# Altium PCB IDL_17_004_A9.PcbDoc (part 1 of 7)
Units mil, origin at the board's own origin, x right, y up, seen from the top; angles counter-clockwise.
Board outline 9493.25 x 7199.68 mil, 6 copper layers (Top Layer - SIG1, Layer 2 - GND1, Layer 3 - PWR1, Layer 4 - PWR2, Layer 5 - GND2, Bottom Layer - SIG2), stack 60.592 mil thick; 403 components, 274 nets, 1834 pads, 1849 vias.
Unrouted connection lines stored in the file: 1.
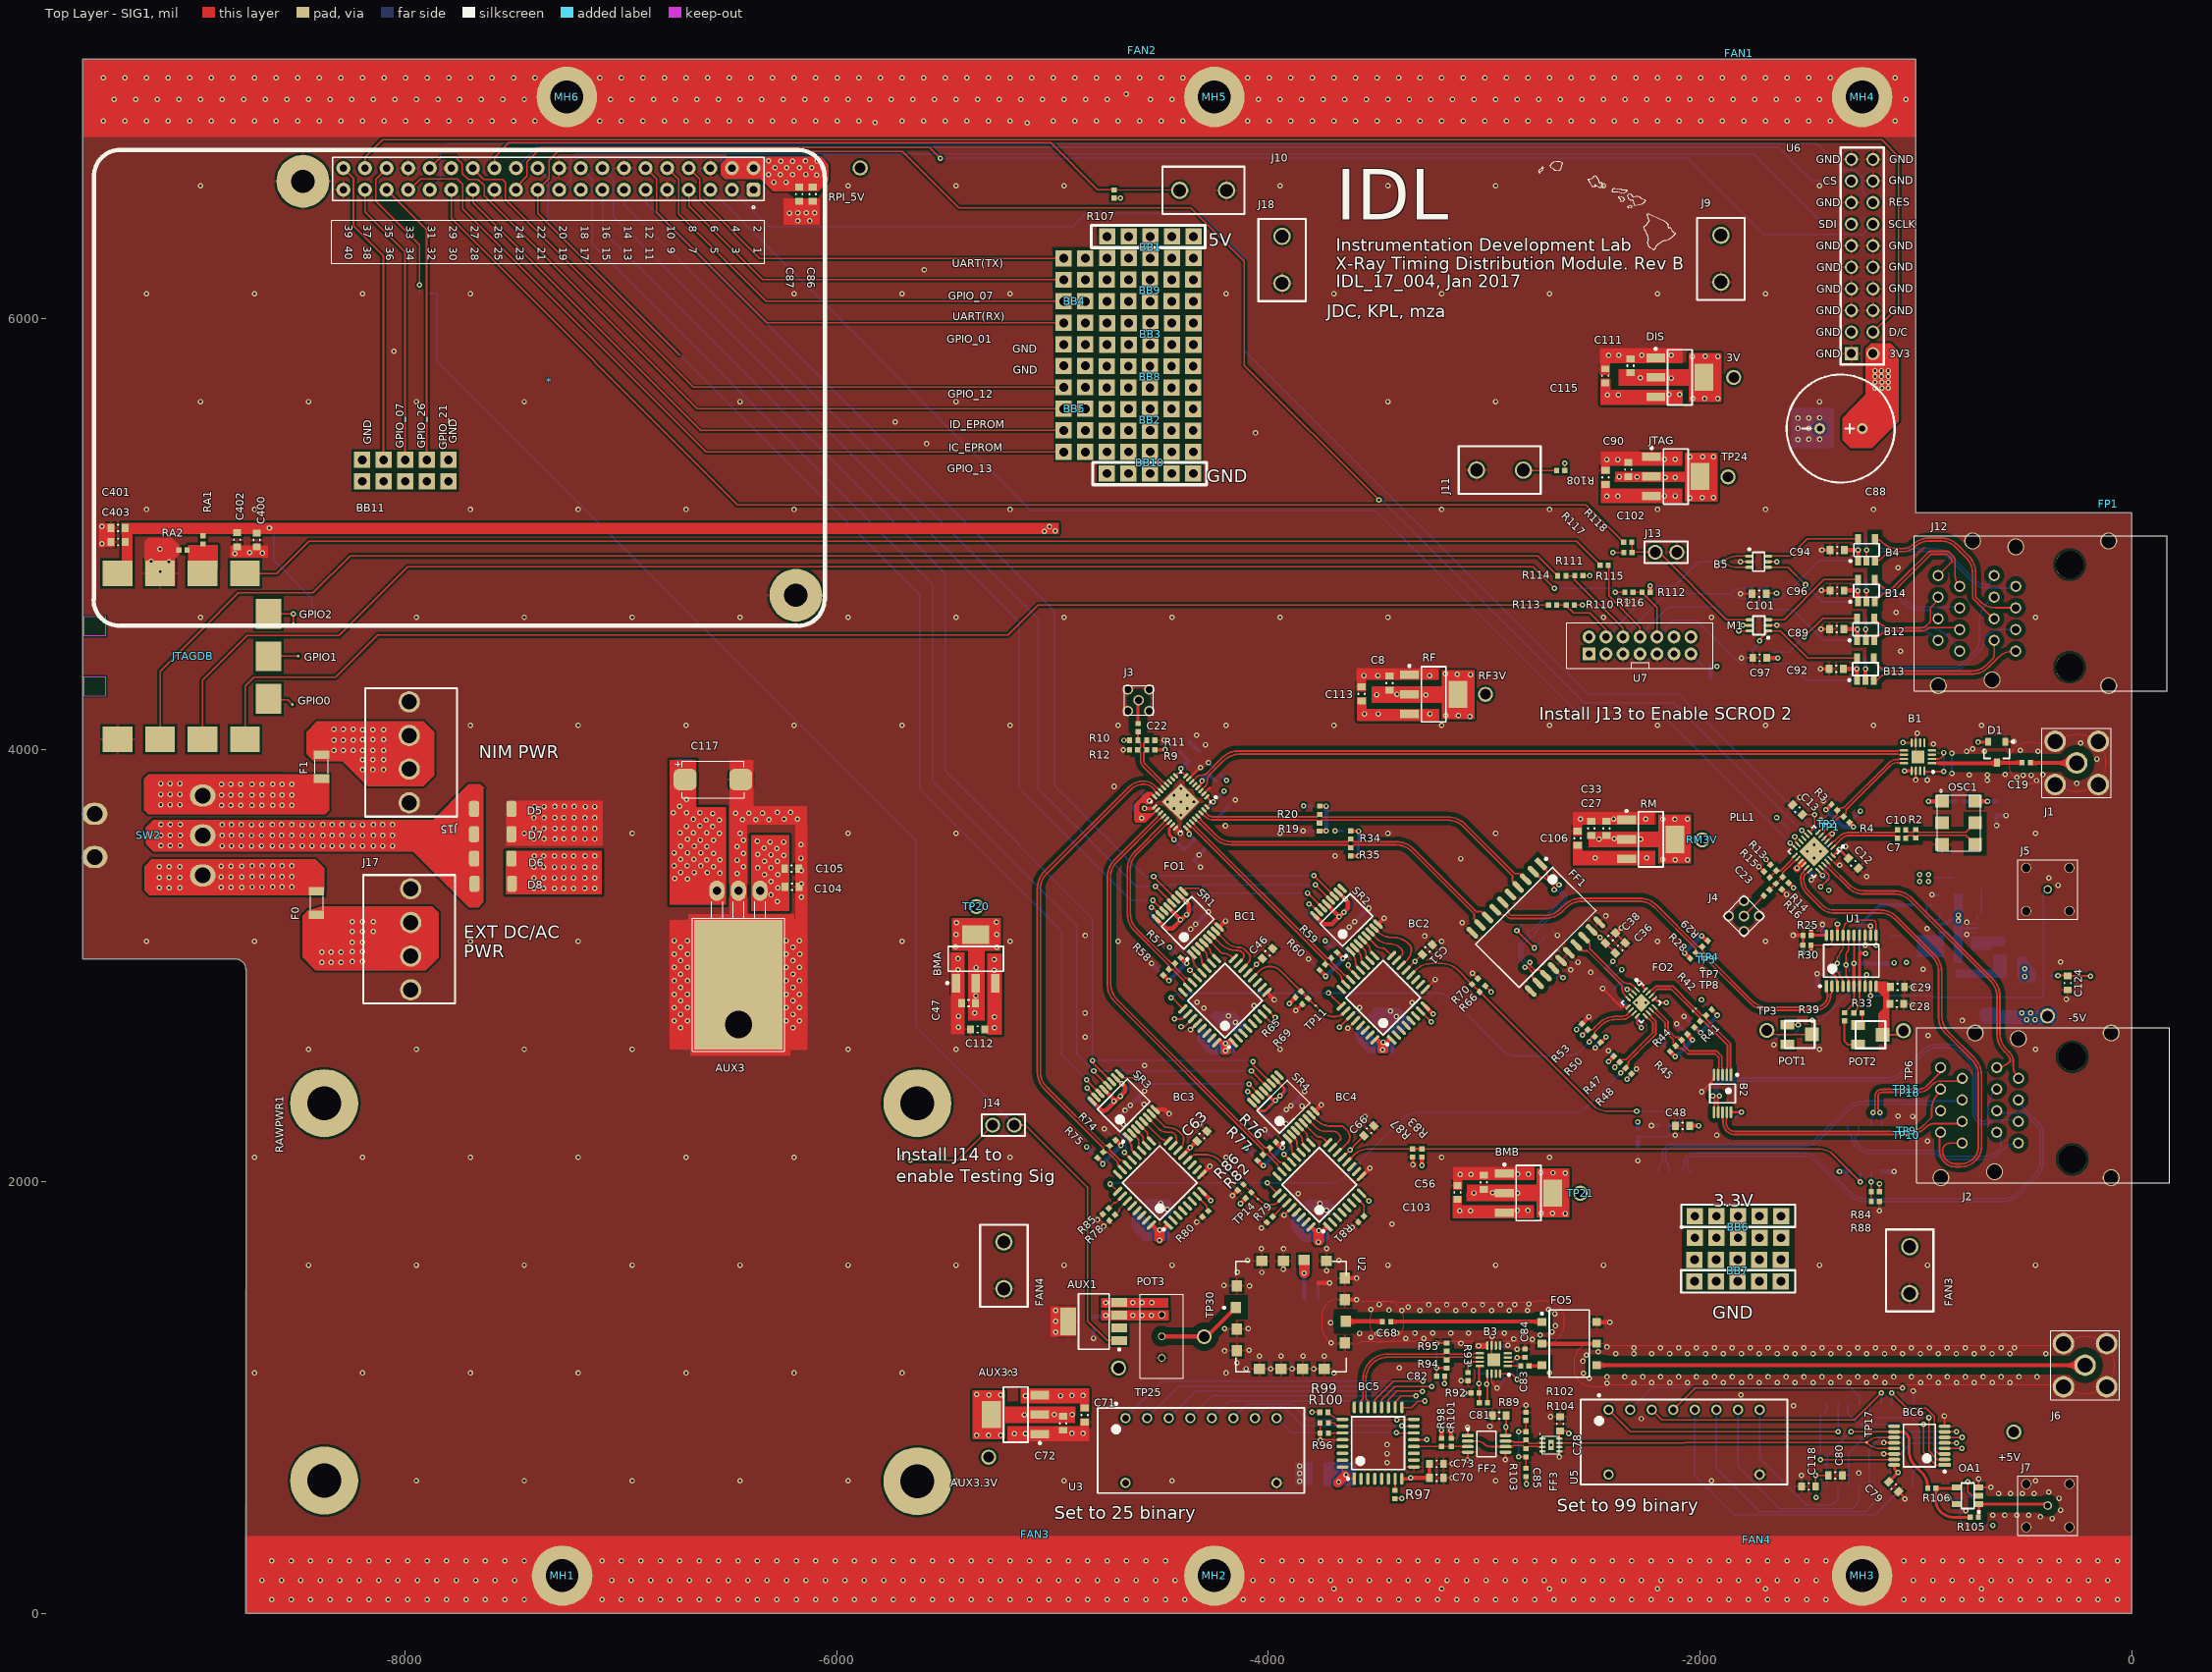
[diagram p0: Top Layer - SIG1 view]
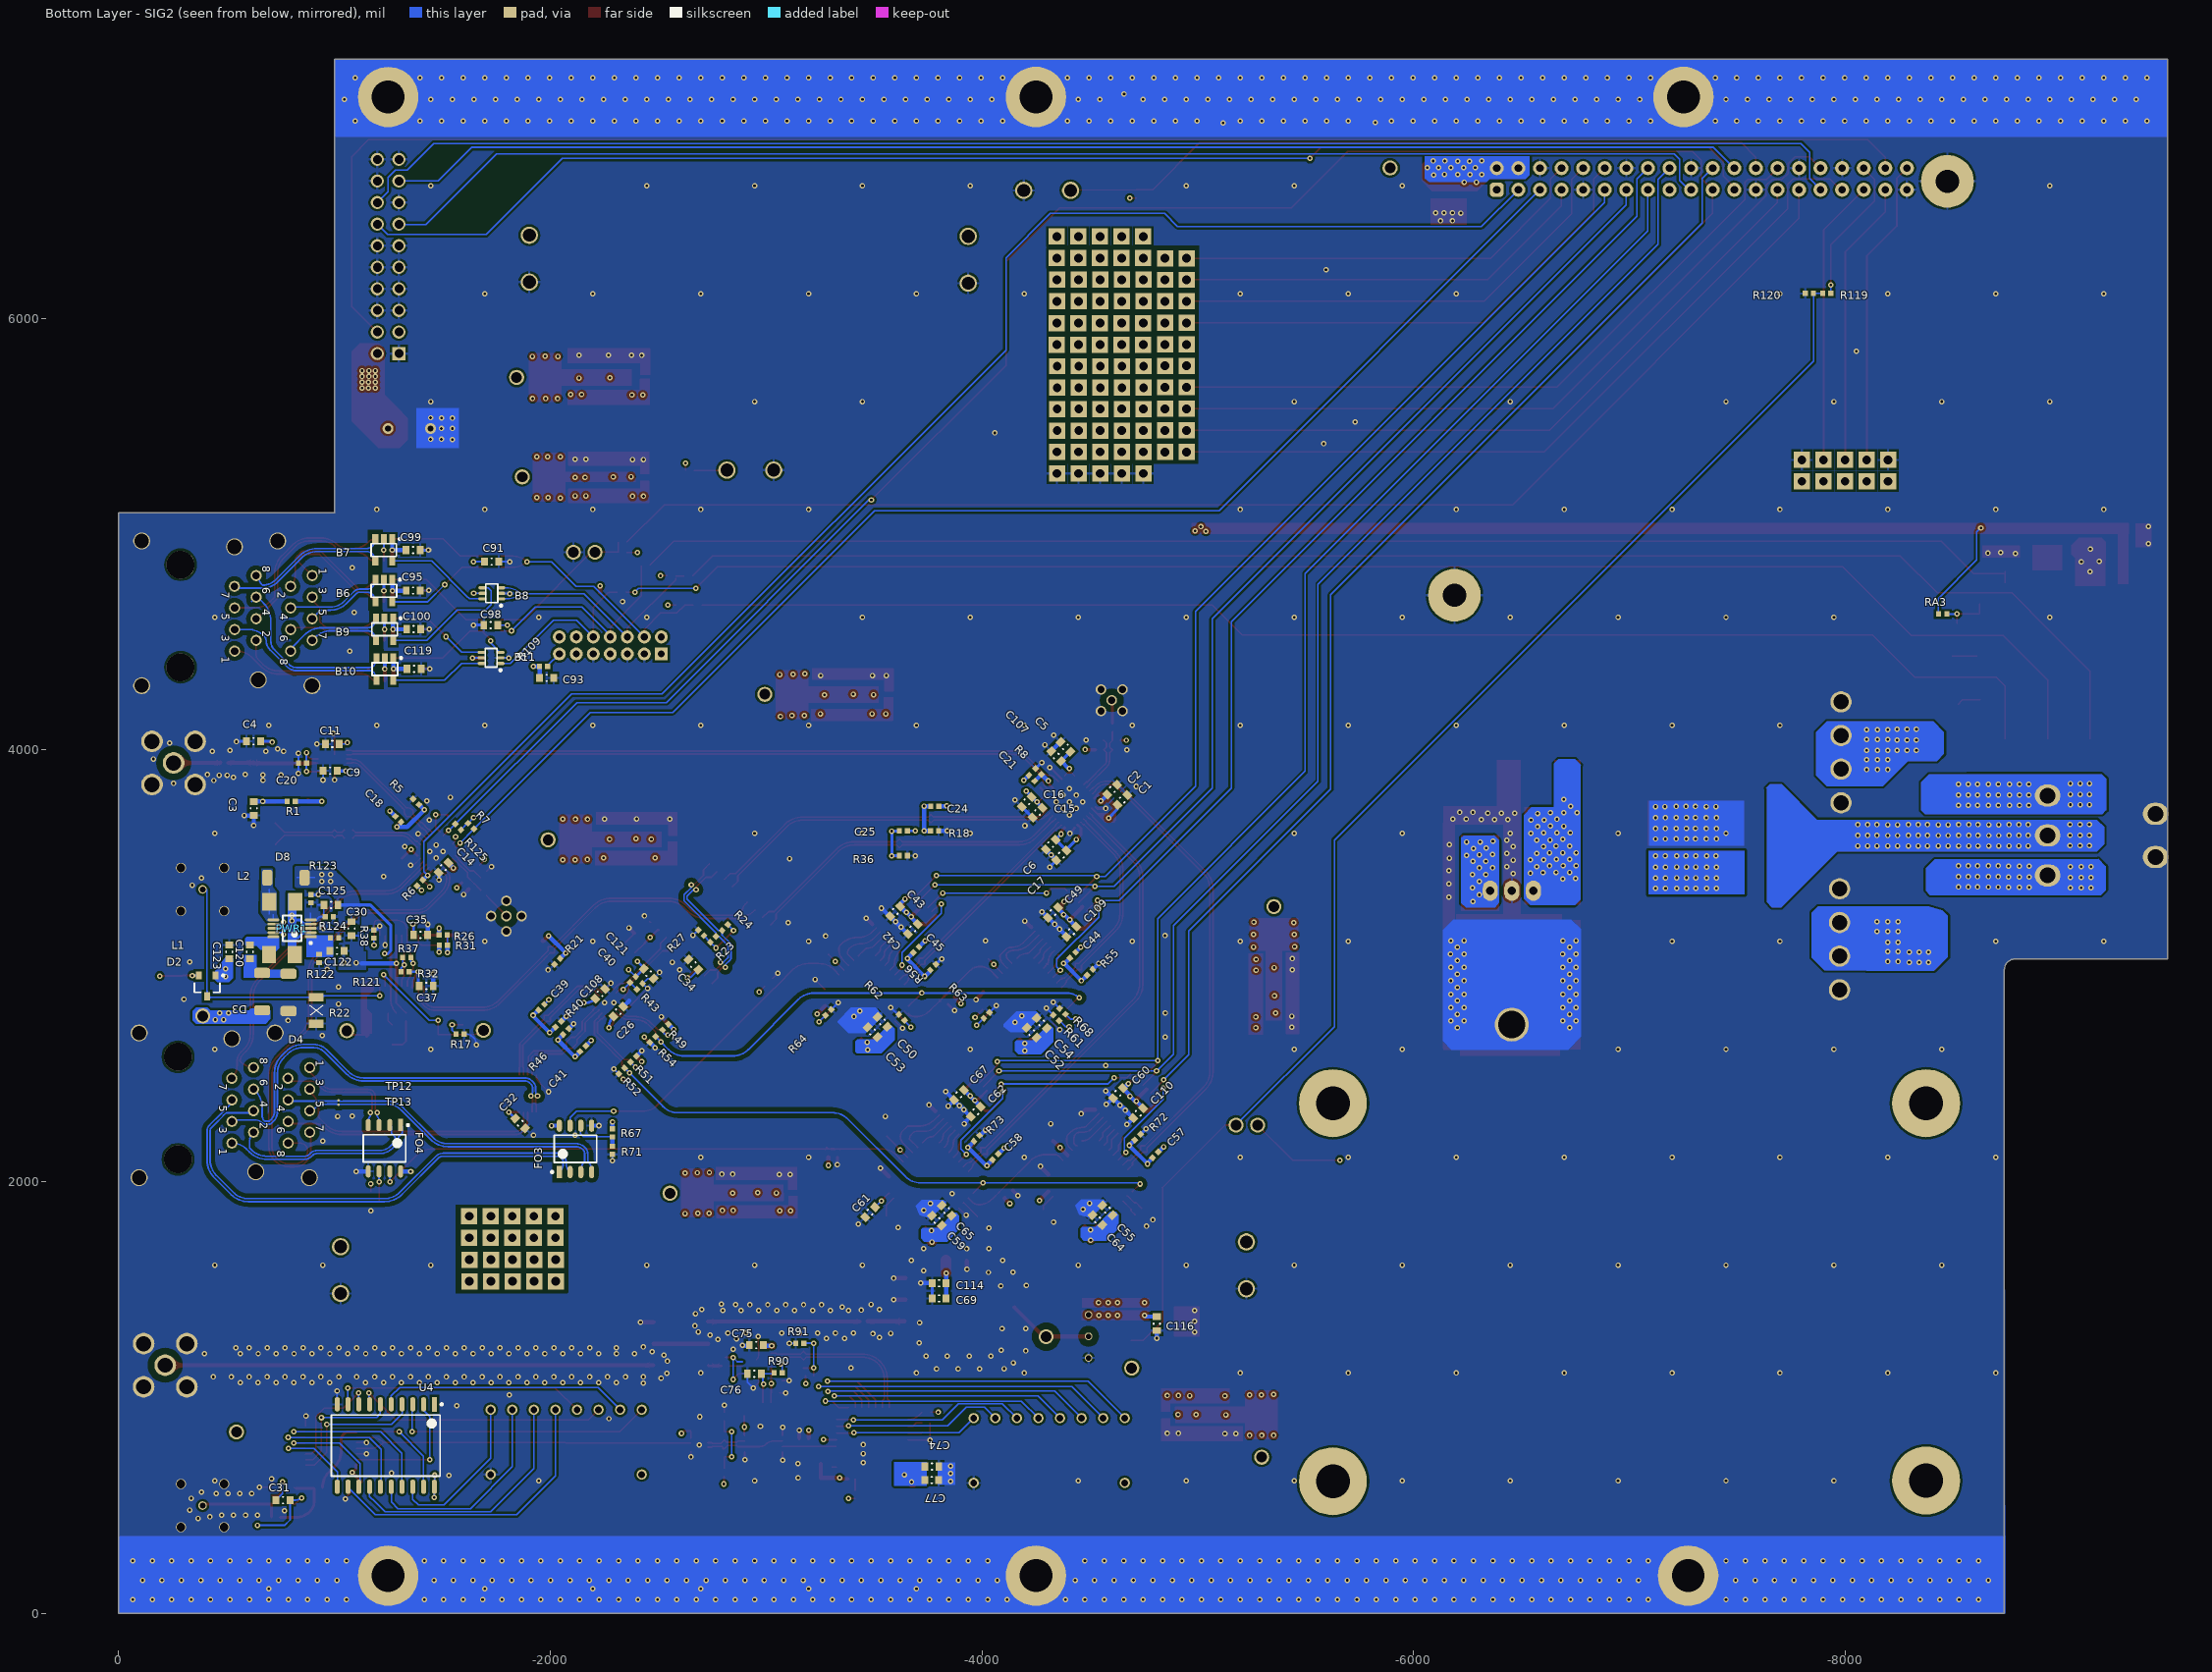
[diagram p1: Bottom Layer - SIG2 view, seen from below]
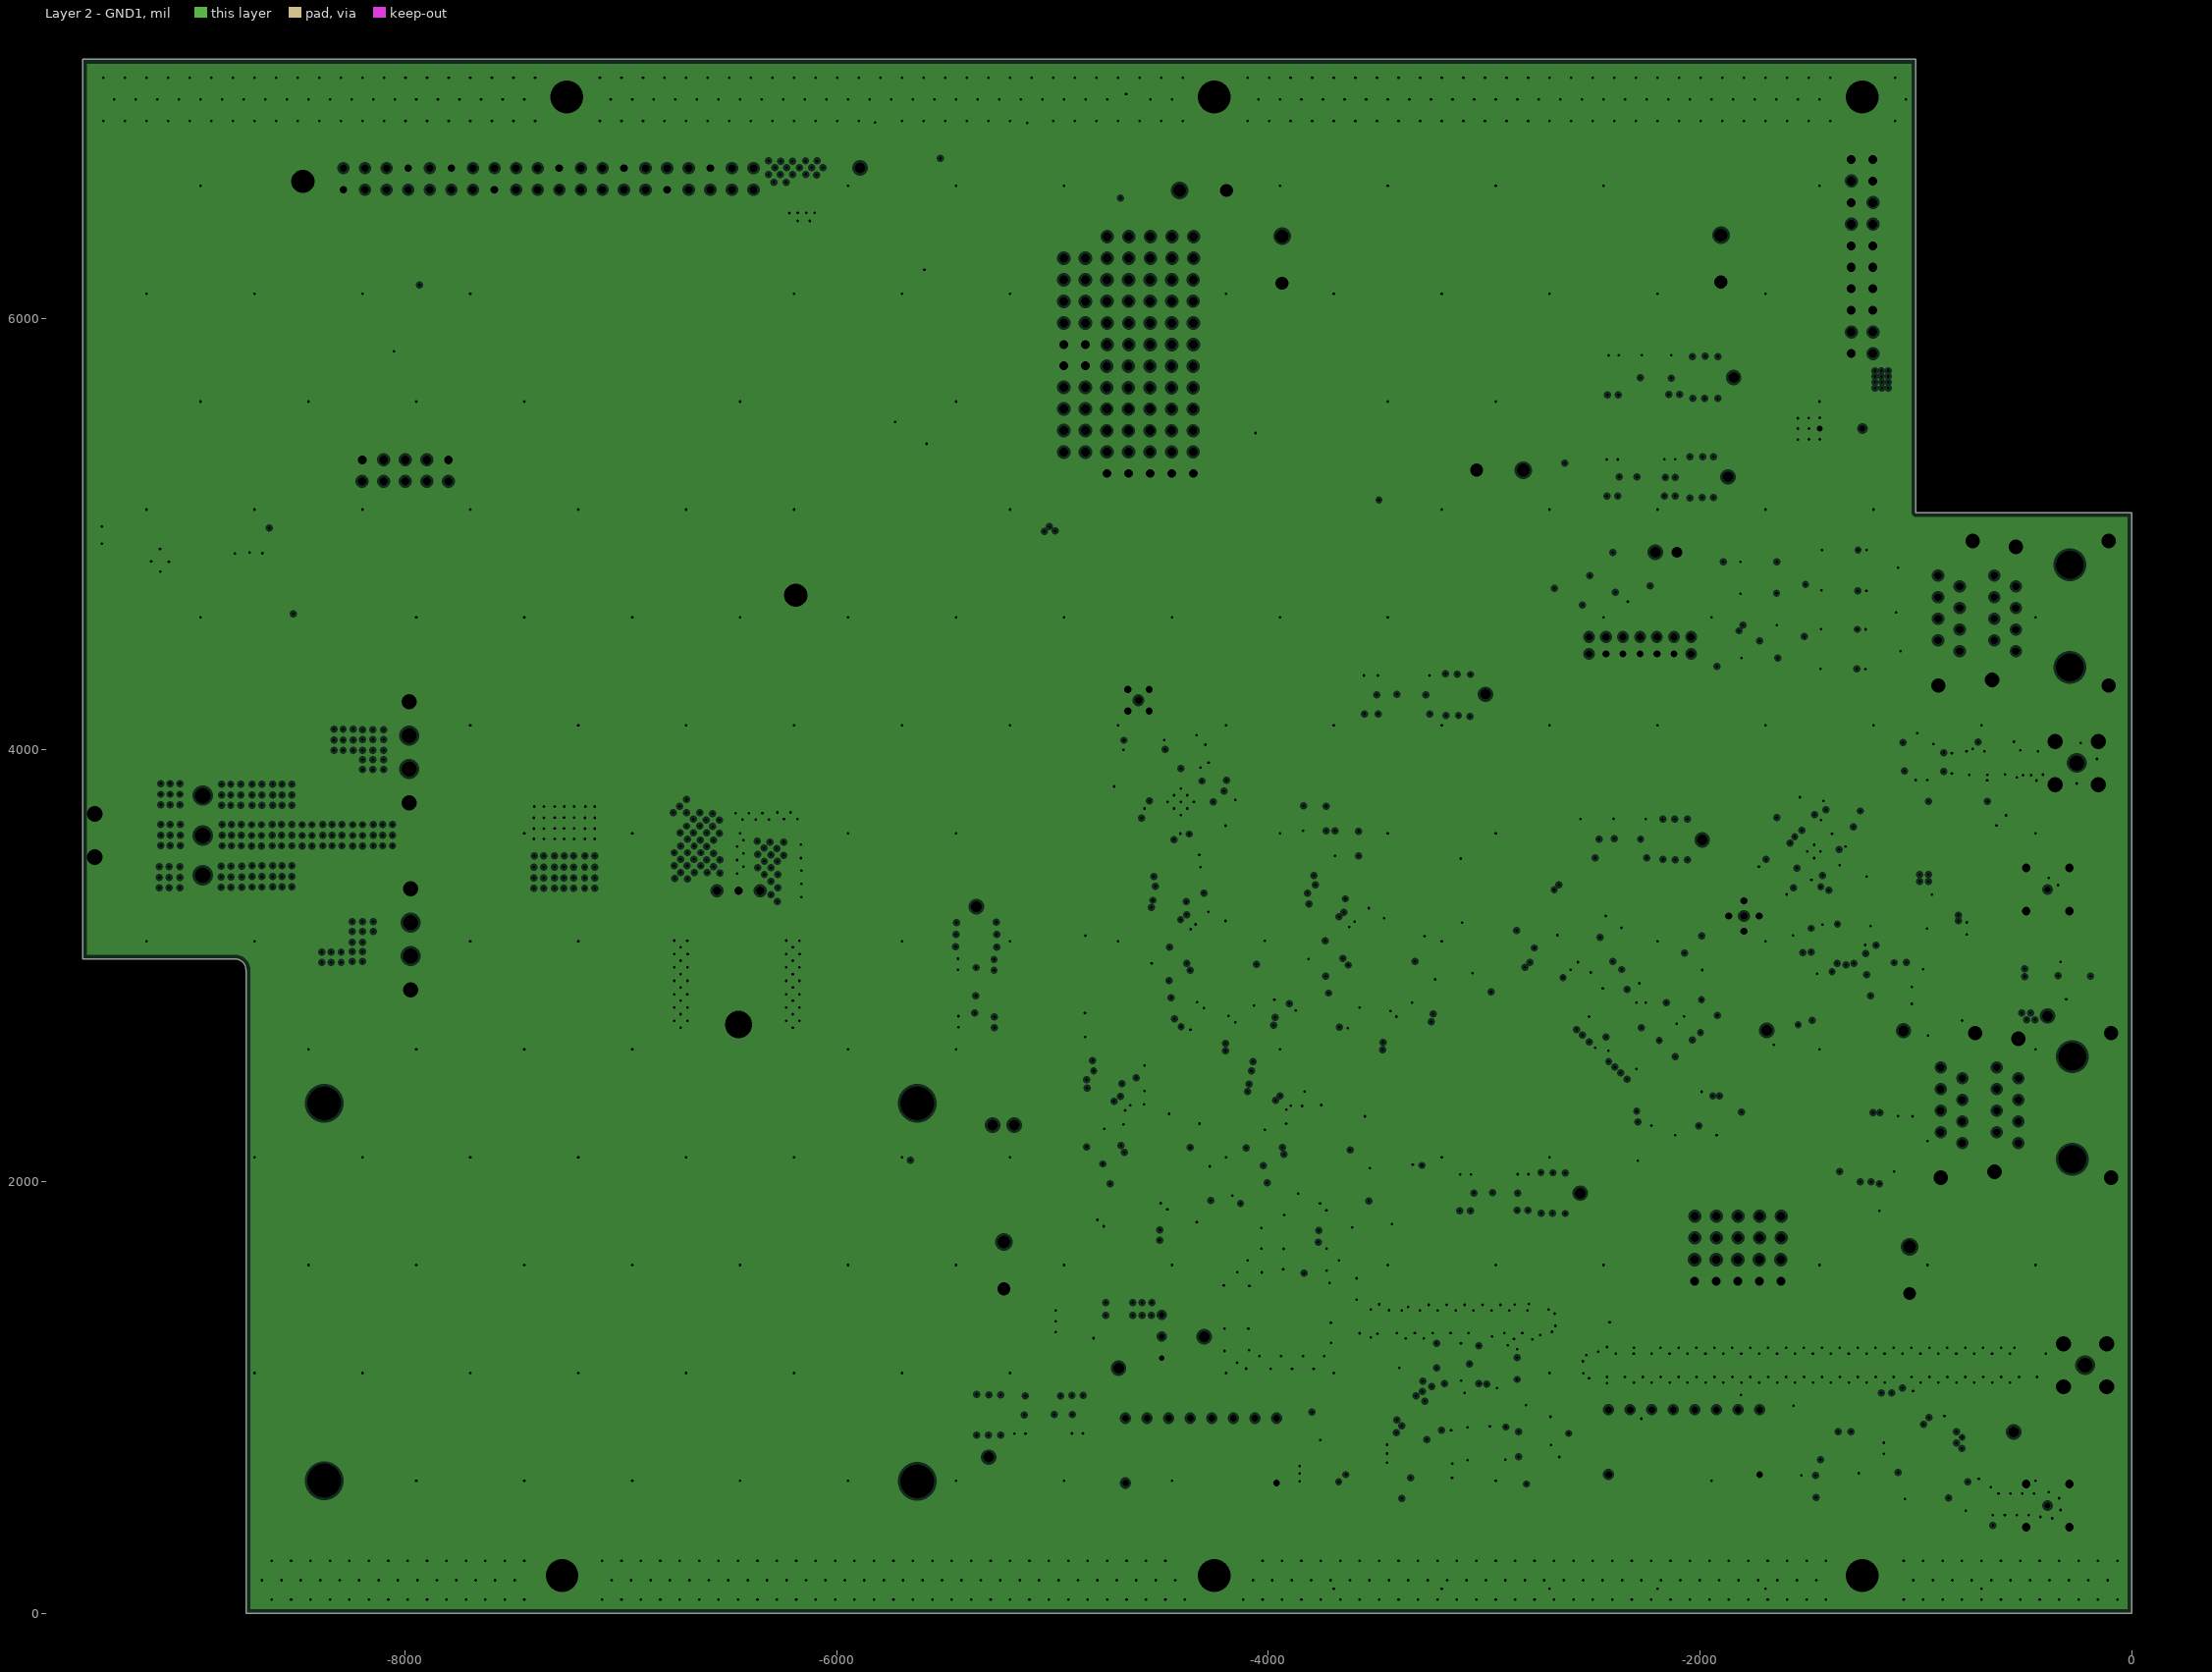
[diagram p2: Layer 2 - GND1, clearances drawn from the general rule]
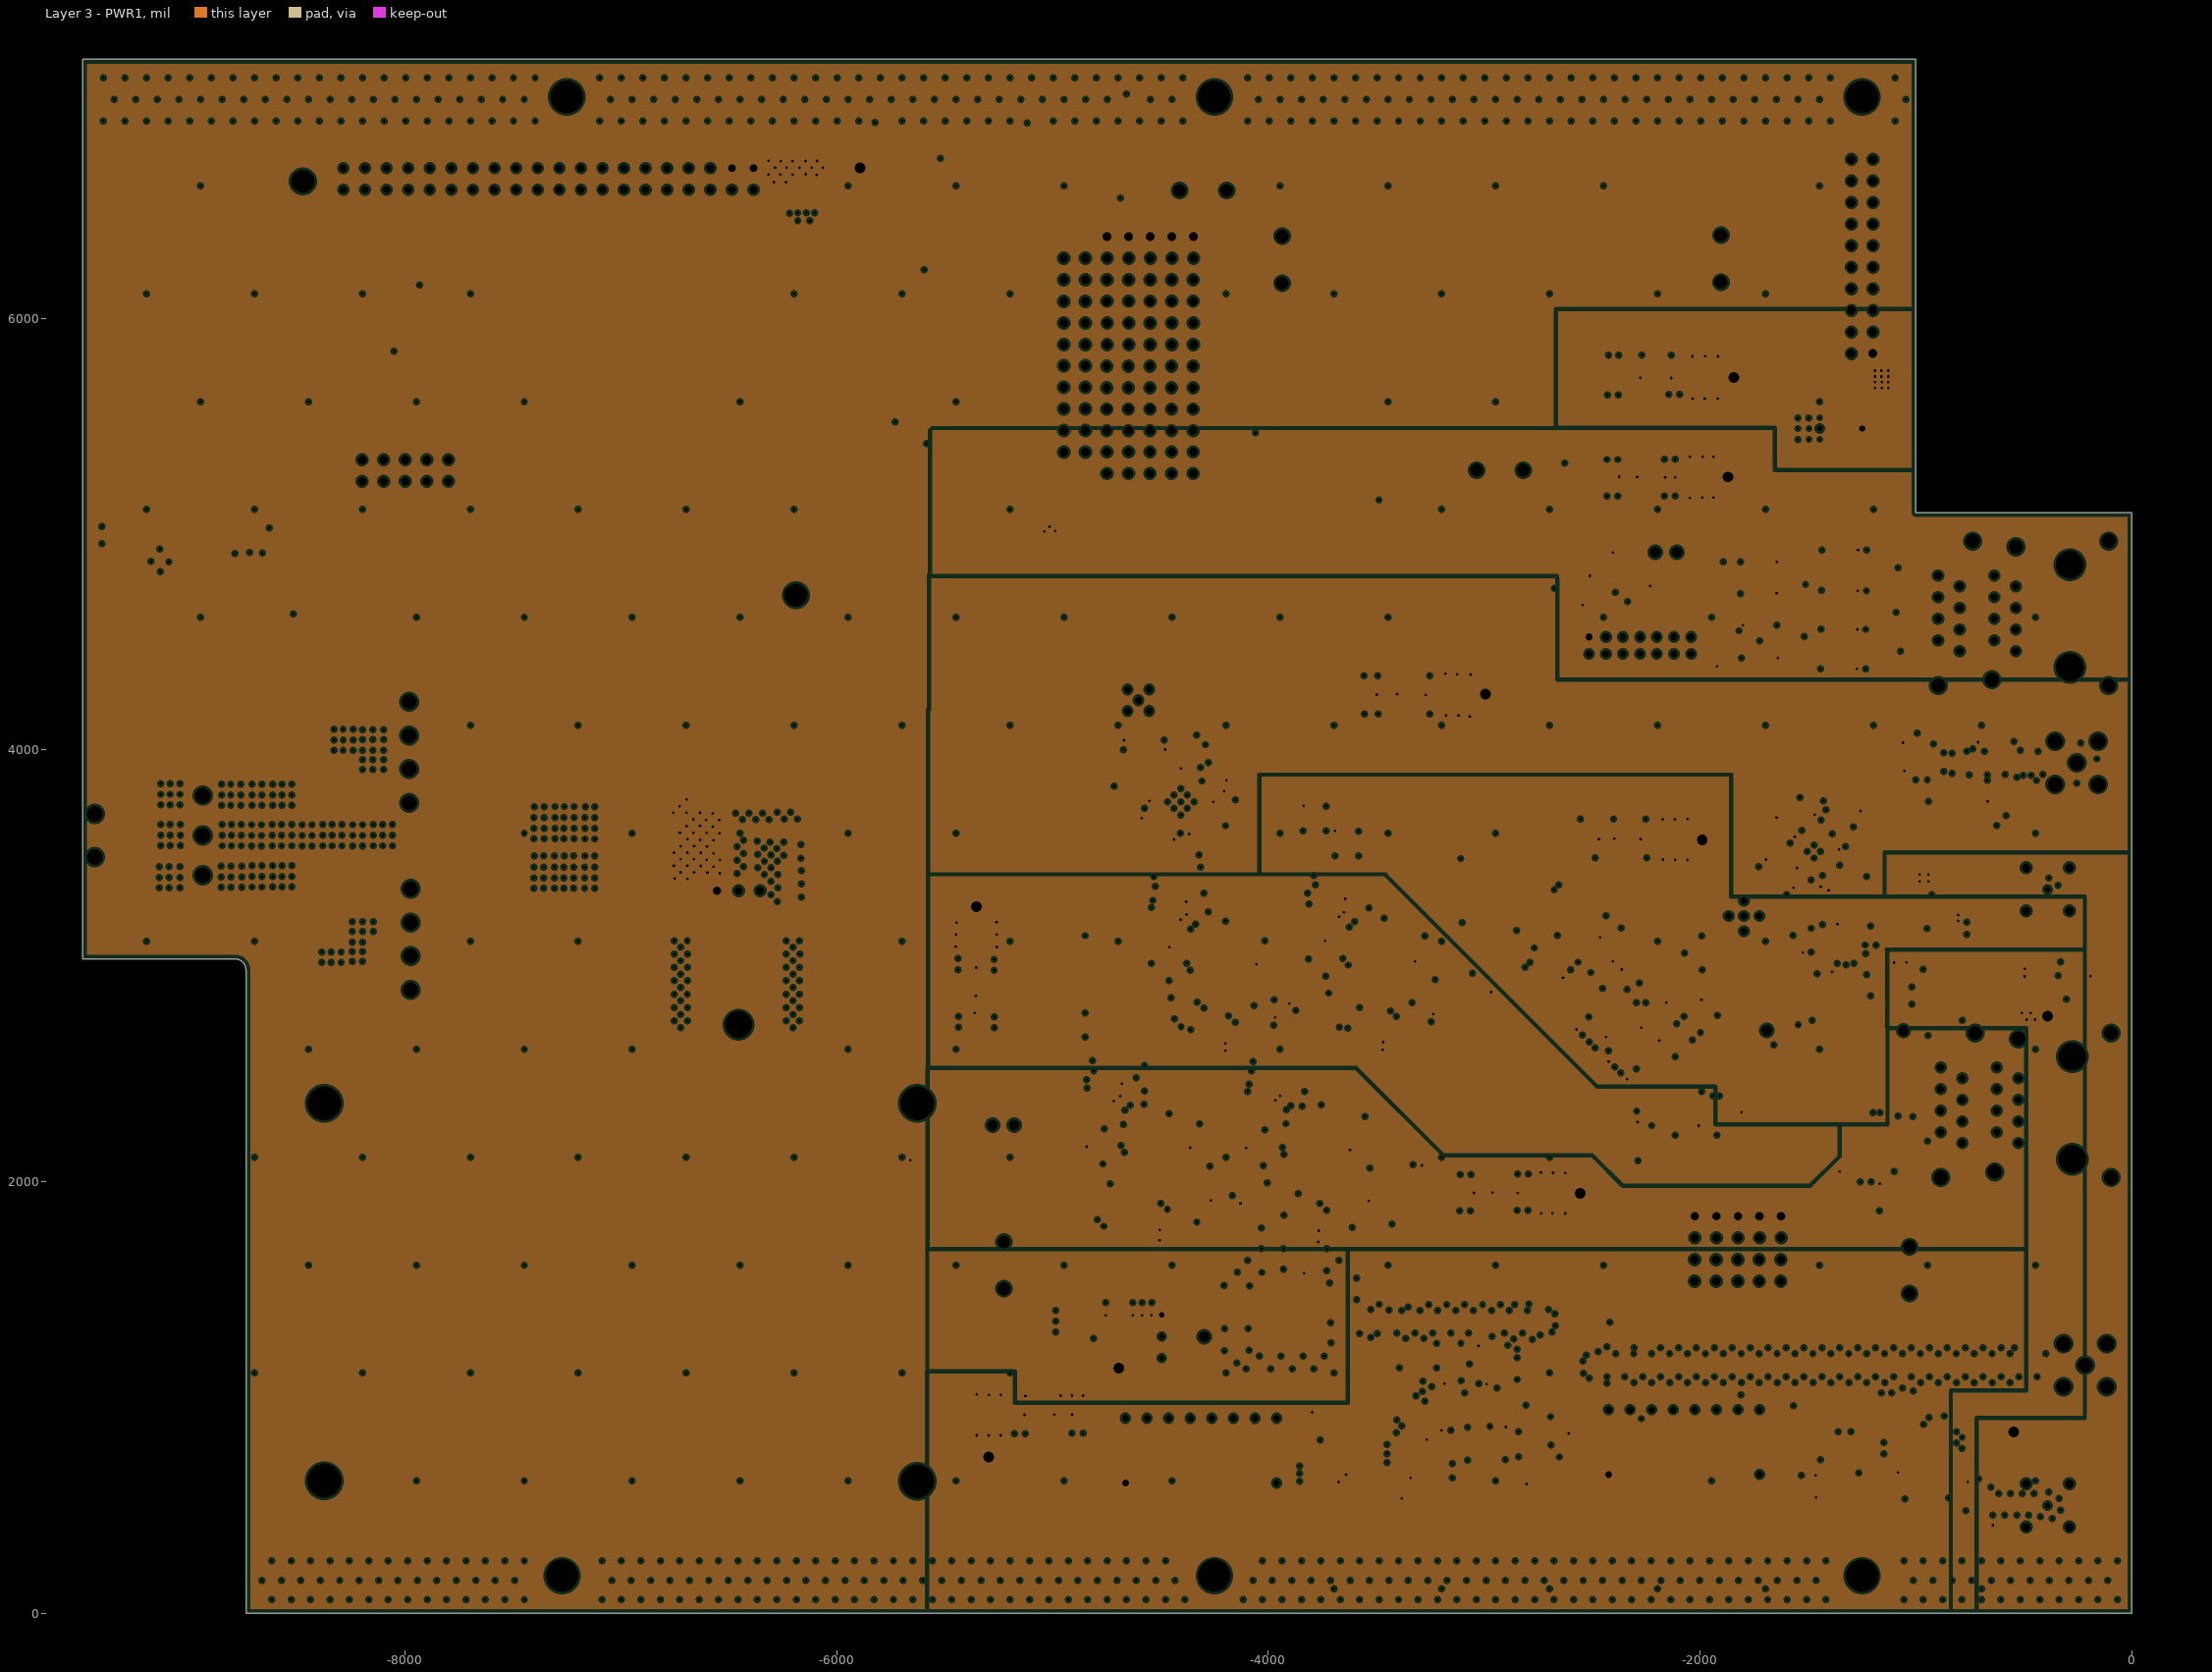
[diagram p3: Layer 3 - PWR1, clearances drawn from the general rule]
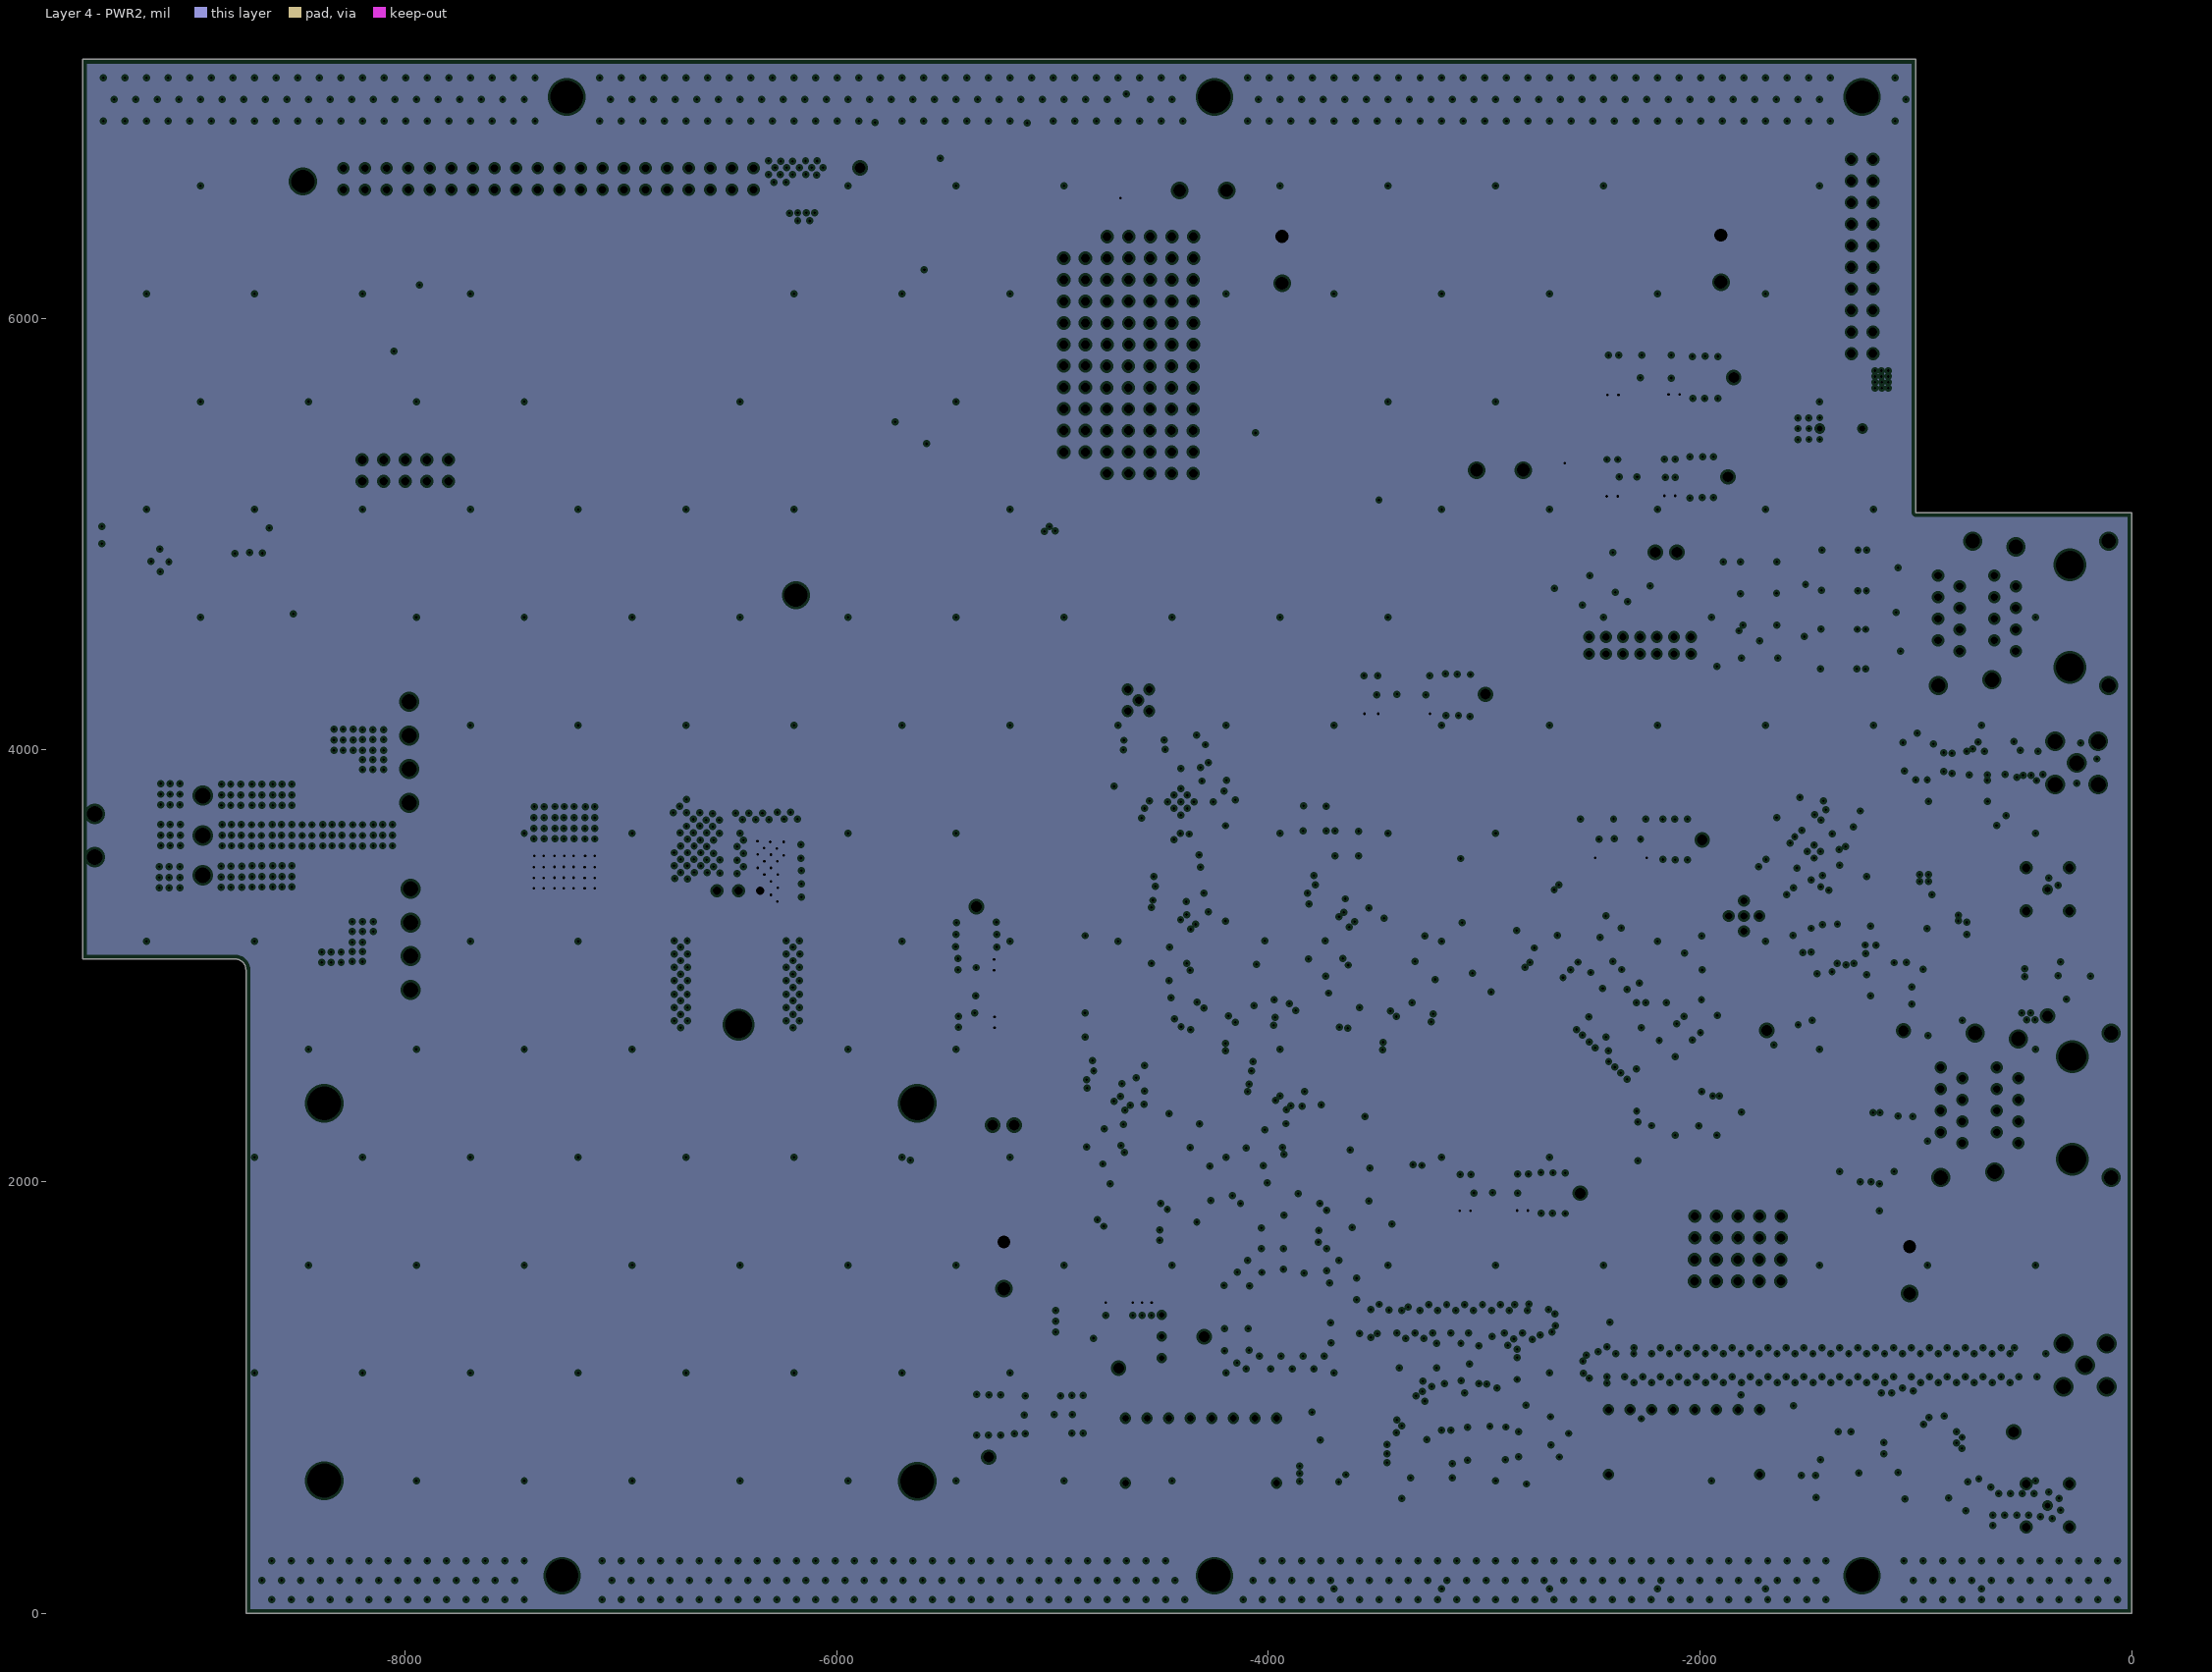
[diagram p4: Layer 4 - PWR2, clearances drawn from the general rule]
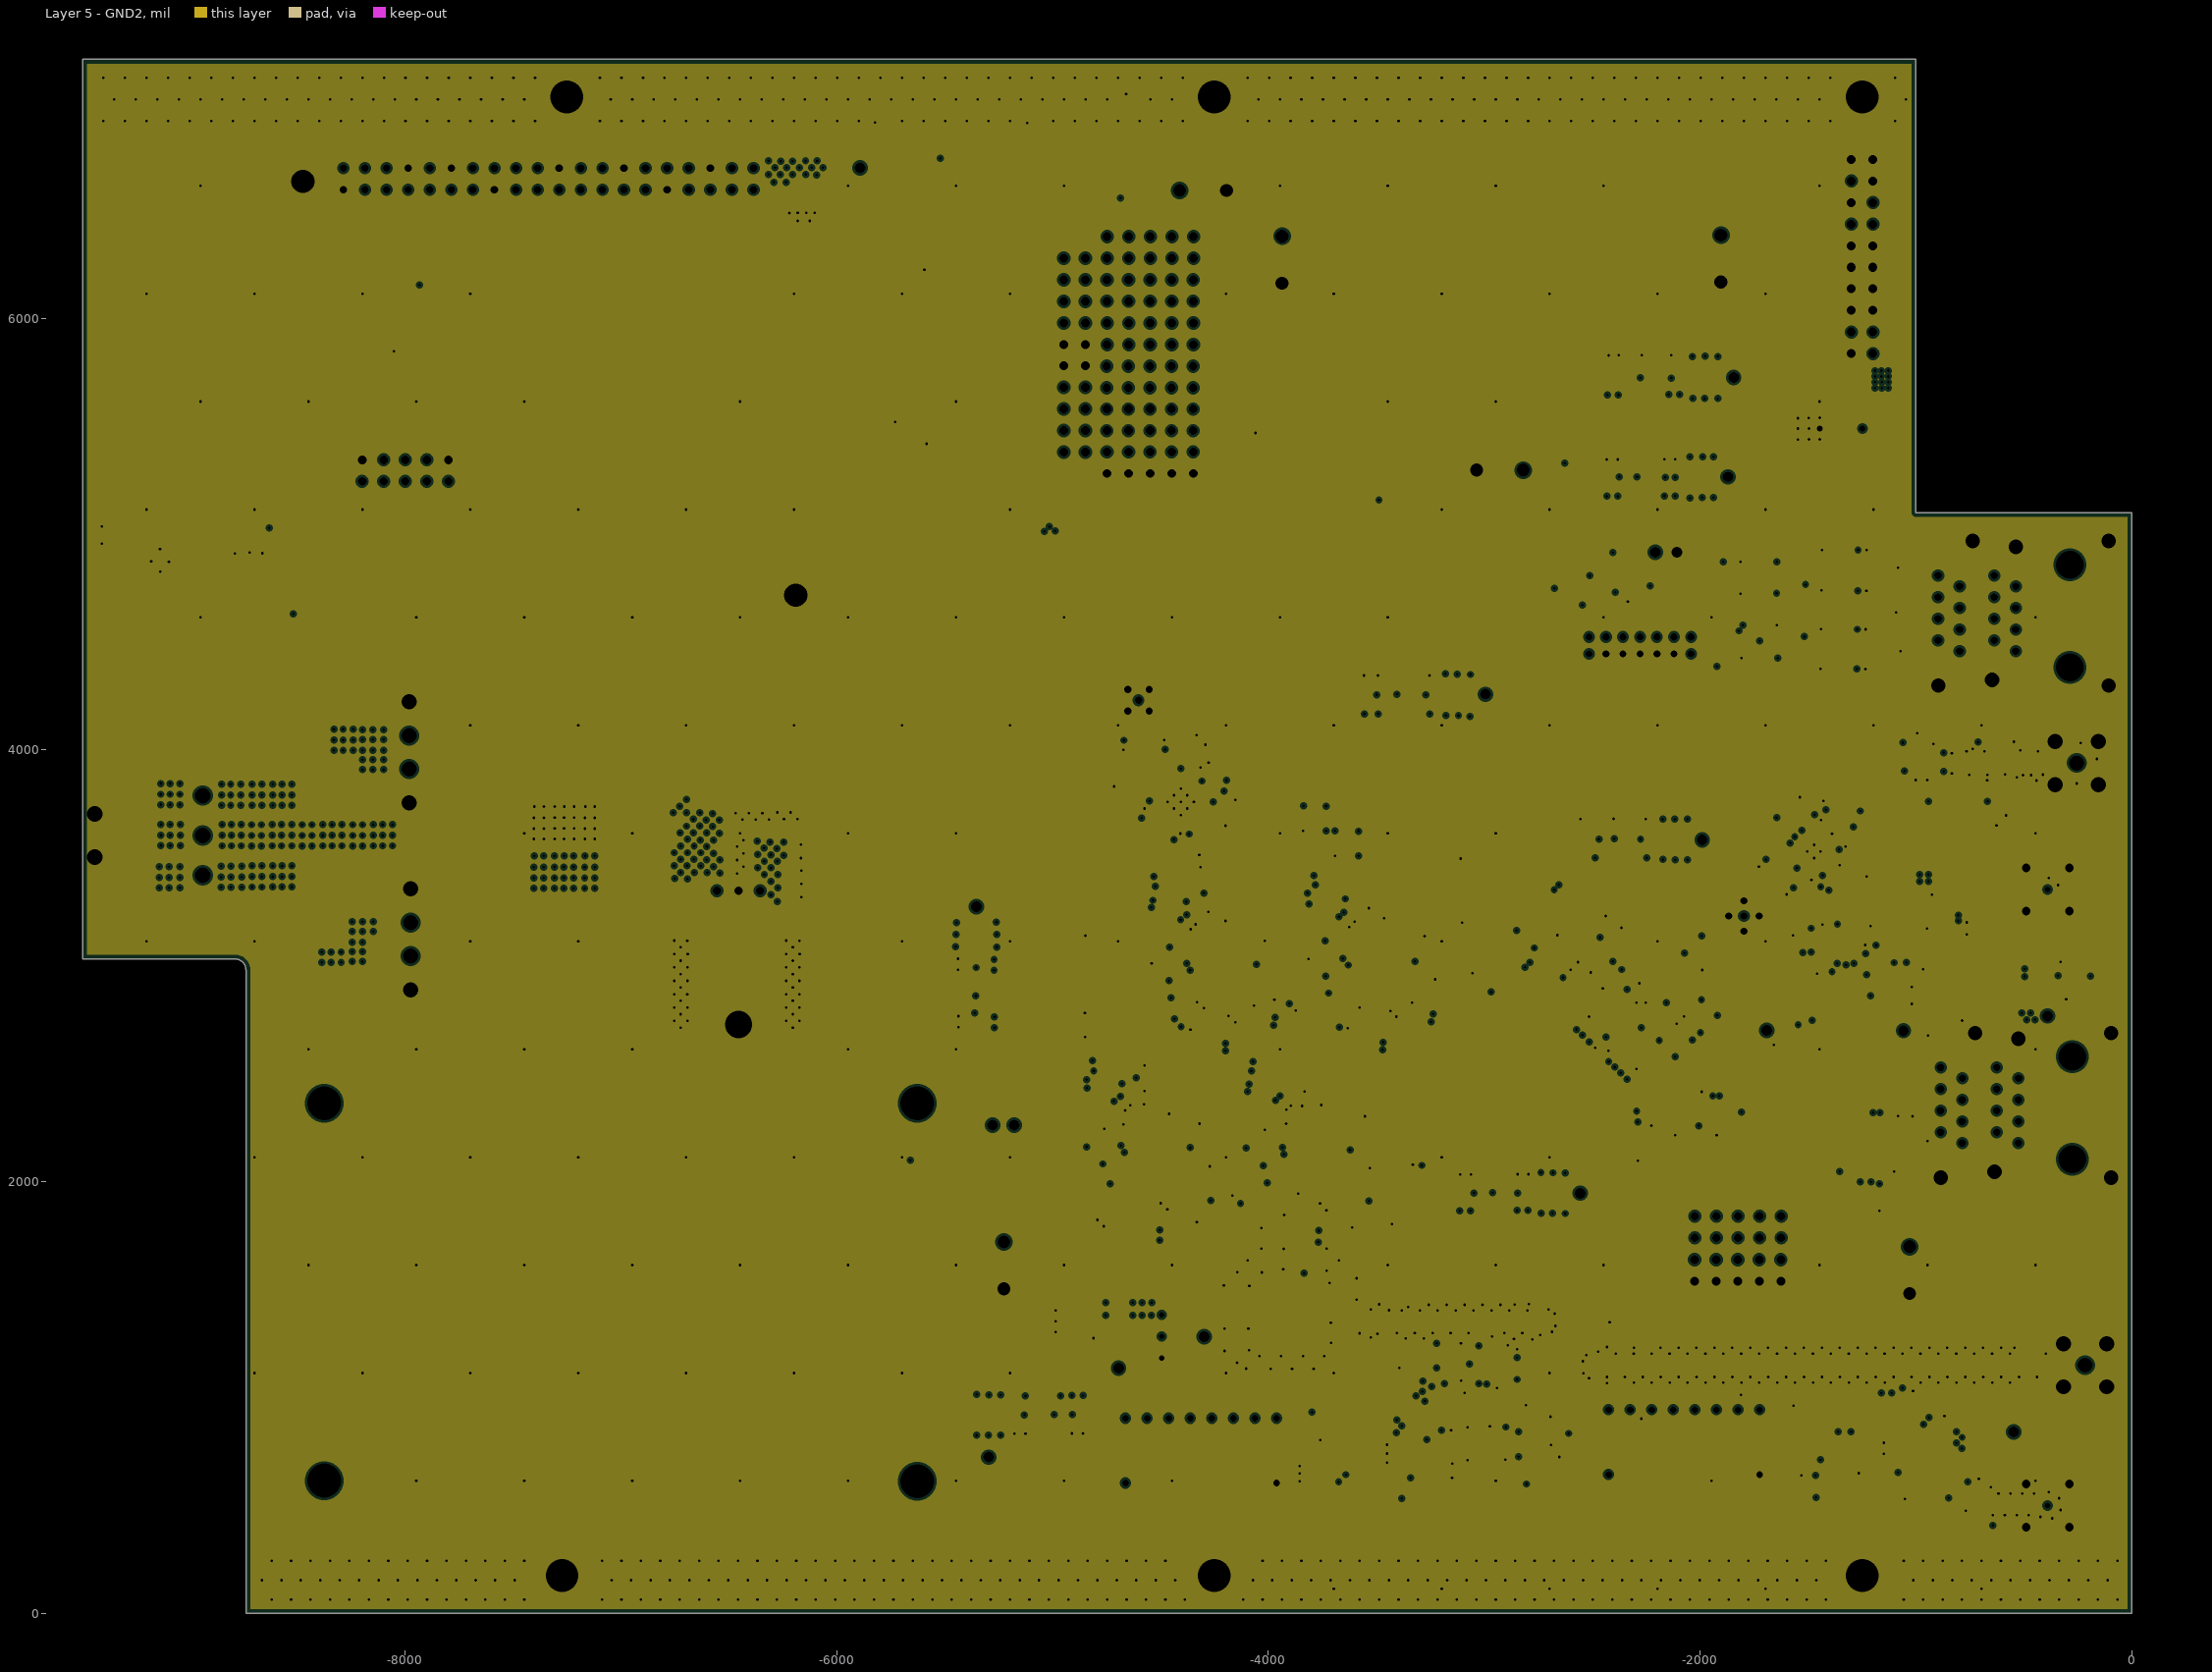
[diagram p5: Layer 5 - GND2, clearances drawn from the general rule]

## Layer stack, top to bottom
Top Solder: solder mask 0.4, Solder Resist, Dk 3.5
Top Layer - SIG1: signal copper 1.378
Dielectric 1: prepreg 9, FR-4, Dk 4.6
Layer 2 - GND1: plane copper 0.709, net GND
Dielectric 2: prepreg 14, FR-4, Dk 4.6
Layer 3 - PWR1: plane copper 0.709, net RPI_5V
Dielectric 3: prepreg 9, FR-4, Dk 4.2
Layer 4 - PWR2: plane copper 0.709, net RAW PWR
Dielectric 4: prepreg 14, FR-4, Dk 4.6
Layer 5 - GND2: plane copper 0.709, net GND
Dielectric 5: prepreg 9, FR-4, Dk 4.6
Bottom Layer - SIG2: signal copper 1.378
Bottom Solder: solder mask 0.4, Solder Resist, Dk 3.5

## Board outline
-0.02,5098.53 -1000.48,5098.53 -1000.48,7199.47 -9493.25,7199.47 -9492.76,3031.36 -8787.25,3032.05 cw(c-8787.25,2981.03) -8736.22,2981.02 -8734.86,2979.66 -8736.22,-0.21 0,0

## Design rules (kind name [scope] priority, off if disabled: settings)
Clearance "Polygon Clearence Rules" [InNet('GND') AND InNamedPolygon('L1-GND') or InNamedPolygon('L6-GND')] p1 off: gap=6
Clearance Clearance_Diff [InAnyDifferentialPair vs InNamedPolygon('L1-GND') or InNamedPolygon('L6-GND')] p2: gap=20
Clearance Clearance_RF [InNetClass('RF') vs InNamedPolygon('L1-GND') or InNamedPolygon('L6-GND')] p3: gap=30
Clearance test [InComponent('BB1') AND InComponent('BB2') AND InComponent('BB3') AND InComponent('BB4') AND InComponent('BB5') AND InComponent('BB6') AND InComponent('BB7')   AND InComponent('BB8') AND InComponent('BB9') AND InComponent('BB10') vs (OnLayer('Bottom Layer - SIG2') AND OnLayer('Top Layer - SIG1'))] p4: gap=50
Clearance Clearance_2 [InNamedPolygon('L1-GND')] p5: gap=10
Clearance Clearance_1 [InNamedPolygon('L1-GND')] p6: gap=15
Clearance Clearance_Poly [InNamedPolygon('L1-GND') or InNamedPolygon('L6-GND')] p7: gap=10
Clearance Clearance_KeepOut [Iskeepout] p8 off: gap=20
Clearance Clearance_3 [All] p9: gap=6
ComponentClearance [All] p1 off: gap=10 collisioncheckmode=3 verticalgap=10 showdistances=FALSE
DiffPairsRouting [All] p1: maxlimit=6 minlimit=6 mostfreqgap=6 toplayer_minwidth=8 toplayer_maxwidth=8 toplayer_prefwidth=8 bottomlayer_minwidth=8 bottomlayer_maxwidth=8 bottomlayer_prefwidth=8 maxuncoupledlength=500
Height [All] p1 off: minheight=0 maxheight=1000 prefheight=500
HoleSize [All] p1: absolutevalues=TRUE maxlimit=250 minlimit=11.81 maxpercent=80.000 minpercent=20.000
MinimumSolderMaskSliver [All] p1: minsoldermaskwidth=5
NetAntennae [All] p1 off: netantennaetolerance=0
PlaneClearance PlaneClearance_1 [(InComponent('BB1') AND InComponent('BB2') AND InComponent('BB3') AND InComponent('BB4') AND InComponent('BB5') AND InComponent('BB6') AND InComponent('BB7')   AND InComponent('BB8') AND InComponent('BB9') AND InComponent('BB10') AND InComponent('BB11'))] p1: clearance=50
PlaneClearance [All] p2: clearance=11
PlaneConnect PlaneConnect_vIA [ISvIA] p1: planeconnectstyle=Direct reliefexpansion=20 reliefentries=4 reliefconductorwidth=10 reliefairgap=10
PlaneConnect [All] p2: planeconnectstyle=Direct reliefexpansion=12 reliefentries=4 reliefconductorwidth=15 reliefairgap=8
PolygonConnect PolygonConnect_Via [IsVia or HasFootprint('MLF_QFN_32PIN') or HasFootprint('SMA_R/A') or HasFootprint('2X1 RJ45') or HasFootprint('MAXB6MPCBV') or HasFootprint('LEMO_R/A') or HasFootprint('MMCX_VERTICAL_THROUGH_HOLE') or HasFootprint('MOLEX 4POS') or HasFootprint('E101SD1AQE') or HasFootprint('SOD128') or HasFootprint('FUSE1206-1') or HasFootprint('1008') or HasFootprint('TFSOP_10pin')] p1: connectstyle=Direct reliefconductorwidth=10 reliefentries=4 polygonreliefangle="90 Angle" airgapwidth=10
PolygonConnect PolygonConnect_Main [All] p2: connectstyle=Relief reliefconductorwidth=12 reliefentries=4 polygonreliefangle="90 Angle" airgapwidth=10
RoutingVias [All] p1: holewidth=11.81 width=25.59 viastyle="Through Hole" minholewidth=11.81 minwidth=25.59 maxholewidth=11.81 maxwidth=25.59
SilkToSilkClearance [All] p1: silktosilkclearance=5
SilkToSolderMaskClearance SilkscreenOverComponentPads [IsPad] p1: minsilkscreentomaskgap=5 clearancetoexposedcopper=TRUE
SolderMaskExpansion [All] p1: expansion=2
Width Width_Logo [HasFootprint('ITECH_LOGO')] p1: maxlimit=14.72 minlimit=14.72 preferedwidth=14.72 impedancedriven=TRUE minimp=50.000000 maximp=50.000000 favimp=50.000000
Width [All] p2: maxlimit=20 minlimit=6 preferedwidth=8 minimp=50.000000 maximp=50.000000 favimp=50.000000
20 further rules are at their usual default settings.

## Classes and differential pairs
net class RF: NetB1_1 NetB3_1 NetC19_1 NetC22_2 NetC23_2 NetC68_1 NetC83_1 NetFO5_4 NetPOT3_2 RFCLK6_N RFCLK6_P RFOUT2_N RFOUT2_P
component class IDL_17_001_A2: B1 C1 C2 C3 C4 C5 C6 C7 C8 C9 C10 C11 C12 C13 C14 C15 C16 C17 C18 C19 C20 C21 C22 C23 D1 FO1 J1 J2 J3 J4 OSC1 PLL1 R1 R2 R3 R4 R5 R6 R7 R8 R9 R10 R11 R12 R13 R14 R15 R16 R125 R? TP1 TP2
component class IDL_17_001_A3: B2 C24 C25 C26 C27 C28 C29 C30 C31 C32 C33 C34 C35 C36 C37 C38 C39 C40 C41 D2 FF1 FO2 J5 POT1 POT2 R17 R18 R19 R20 R21 R22 R23 R24 R25 R26 R27 R28 R29 R30 R31 R32 R33 R34 R35 R36 R37 R38 R39 R40 R41 R42 R43 R44 R45 R46 R47 R48 R49 R50 R51 R52 R53 R54 TP3 TP4 TP5 TP6 TP7 TP8 TP9 TP10 U1
component class IDL_17_001_A4: BC1 BC2 BC3 BC4 C42 C43 C44 C45 C46 C47 C48 C49 C50 C51 C52 C53 C54 C55 C56 C57 C58 C59 C60 C61 C62 C63 C64 C65 C66 C67 FO3 FO4 R55 R56 R57 R58 R59 R60 R61 R62 R63 R64 R65 R66 R67 R68 R69 R70 R71 R72 R73 R74 R75 R76 R77 R78 R79 R80 R81 R82 R83 R84 R86 R87 R88 SR1 SR2 SR3 SR4 TP11 TP12 TP13 TP14 TP15 TP16
component class IDL_17_001_A5: B3 BC5 BC6 C68 C69 C70 C71 C72 C73 C74 C75 C76 C77 C78 C79 C80 C81 C82 C83 C84 C85 FF2 FF3 FO5 J6 J7 OA1 POT3 R89 R90 R91 R92 R93 R94 R95 R96 R97 R98 R99 R100 R101 R102 R103 R104 R105 R106 TP17 TP30 U2 U3 U4 U5
component class IDL_17_001_A6: * BB1 BB2 BB3 BB4 BB5 BB6 BB7 BB8 BB9 BB10 BB11 C86 C87 C88 C400 C401 C402 C403 FAN1 FAN2 FAN3 FAN4 FP1 GPIO0 GPIO1 GPIO2 J9 J10 J11 J18 J20 J21 JTAGDB MH1 MH2 MH3 MH4 MH5 MH6 R107 R108 RA1 RA2 RA3 RAWPWR1 U6
component class IDL_17_001_A7: B4 B5 B6 B7 B8 B9 B10 B11 B12 B13 B14 C89 C90 C91 C92 C93 C94 C95 C96 C97 C98 C99 C100 C101 J12 J13 M1 R109 R110 R111 R112 R113 R114 R115 R116 R117 R118 U7
component class IDL_17_001_A8: AUX1 AUX2 AUX3 BMA BMB C102 C103 C104 C105 C106 C107 C108 C109 C110 C111 C112 C113 C114 C115 C116 C117 C118 C119 C120 C121 C122 C123 C124 C125 D3 D4 D5 D6 D7 D8 DIS F0 F1 J14 J15 J17 JTAG L1 L2 PWR1 R119 R120 R121 R122 R123 R124 RF RM SW2 TP18 TP19 TP20 TP21 TP22 TP23 TP24 TP25 TP27 TP28 TP?
differential pair "TEST RF CLK-2": +"TEST RF CLK-2_P" -"TEST RF CLK-2_N"
differential pair DD1_Q0: +DD1_Q0_P -DD1_Q0_N
differential pair RVM2: +RVM2_P -RVM2_N
differential pair BMA2: +BMA2_P -BMA2_N
differential pair BMB2: +BMB2_P -BMB2_N
differential pair BMB1: +BMB1_P -BMB1_N
differential pair BMA1: +BMA1_P -BMA1_N
differential pair RVM_FO1-1: +RVM_FO1-1_P -RVM_FO1-1_N
differential pair "TEST RF CLK-1": +"TEST RF CLK-1_P" -"TEST RF CLK-1_N"
differential pair RFCLK5-1: +RFCLK5-1_P -RFCLK5-1_N
differential pair RFCLK4-1: +RFCLK4-1_P -RFCLK4-1_N
differential pair RFCLK3-1: +RFCLK3-1_P -RFCLK3-1_N
differential pair RFCLK2-1: +RFCLK2-1_P -RFCLK2-1_N
differential pair VCO1-1: +VCO1-1_P -VCO1-1_N
differential pair RVM_FO0-1: +RVM_FO0-1_P -RVM_FO0-1_N
differential pair RFCLK1-1: +RFCLK1-1_P -RFCLK1-1_N
differential pair RFCLK0-1: +RFCLK0-1_P -RFCLK0-1_N
differential pair MRFCLK1-2: +MRFCLK1-2_P -MRFCLK1-2_N
differential pair VCO1: +VCO1_P -VCO1_N
differential pair RFOUT1: +RFOUT1_P -RFOUT1_N
differential pair RFOUT0: +RFOUT0_P -RFOUT0_N
differential pair RFCLK6: +RFCLK6_P -RFCLK6_N
differential pair DD1_Q0: +SYNC_RM_P -SYNC_RM_N
differential pair RVM_FO2: +RVM_FO2_P -RVM_FO2_N
differential pair RVM_FO3: +RVM_FO3_P -RVM_FO3_N
differential pair TCK1: +TCK1_P -TCK1_N
differential pair TCK2: +TCK2_P -TCK2_N
differential pair TDI1: +TDI1_P -TDI1_N
differential pair TDI2: +TDI2_P -TDI2_N
differential pair TDO1: +TDO1_P -TDO1_N
differential pair TMS1: +TMS1_P -TMS1_N
differential pair TMS2: +TMS2_P -TMS2_N
differential pair RMOUT0: +RMOUT0_P -RMOUT0_N
differential pair RMOUT1: +RMOUT1_P -RMOUT1_N
differential pair TDO2: +TDO2_P -TDO2_N
differential pair MRFCLK2: +MRFCLK2_P -MRFCLK2_N
differential pair RFOUT2: +RFOUT2_P -RFOUT2_N

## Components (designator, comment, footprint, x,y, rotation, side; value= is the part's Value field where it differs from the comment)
3V "DIS3V3" "Test Point" -1844.8,5726 r0 top (schematic designator TP22)
* "CN_S7123-ND_2x20pin_RPI2_GPIO" RPI_2/RPI_3 -6055,6780 r180 top locked
+5V "+5V" "Test Point" -547,841 r180 top (schematic designator TP28)
-5V "-5V" "Test Point" -391,2768 r90 top (schematic designator TP27)
AUX1 "LP38692(5V REG W EN)" SOT223_5pin -4808.71,1352.64 r180 top
AUX3 "LT1084CT-5" TO220H -6455,3038 r180 top
AUX3.3 "ADP3338(3V3 REG)" ADP3338 -5171.01,921.24 r180 top (schematic designator AUX2)
AUX3.3V "TEST3V3" "Test Point" -5296.12,724 r90 top (schematic designator TP23)
B1 "ADCLK925BCPZ-R7(Sine-LVPECL)" QFN_16pin -991,3968.53 r180 top
B2 "SY55855VKG(LVPECL-LVDS)" TFSOP_10pin -1896.47,2408.68 r270 top
B3 "ADCLK925BCPZ-R7(Sine-LVPECL)" QFN_16pin -2956.12,1175.91 r180 top
B4 "SN65LVDS1DBVR(LVTTL-LVDS)" SOT23_5PIN -1229.37,4926.26 r90 top
B5 "SN74LVC2G34DCKR(TTL-TTL BUFFER)" TSSOP_6PIN -1729,4872.16 r0 top
B6 "SN65LVDS1DBVR(LVTTL-LVDS)" SOT23_5PIN -1230,4738 r270 bottom locked
B7 "SN65LVDS1DBVR(LVTTL-LVDS)" SOT23_5PIN -1229.37,4926.26 r270 bottom
B8 "SN74LVC2G34DCKR(TTL-TTL BUFFER)" TSSOP_6PIN -1729.52,4725.75 r0 bottom
B9 "SN65LVDS1DBVR(LVTTL-LVDS)" SOT23_5PIN -1233,4559 r270 bottom
B10 "SN65LVDS1DBVR(LVTTL-LVDS)" SOT23_5PIN -1234.4,4374.81 r270 bottom
B11 "SN74LVC2G34DCKR(TTL-TTL BUFFER)" TSSOP_6PIN -1726.52,4426.75 r0 bottom
B12 "SN65LVDS1DBVR(LVTTL-LVDS)" SOT23_5PIN -1233,4559 r90 top
B13 "SN65LVDT2DBVR(LVDS-LVTTL)" SOT23_5PIN -1234.4,4374.81 r90 top locked
B14 "SN65LVDT2DBVR(LVDS-LVTTL)" SOT23_5PIN -1230,4738 r90 top locked
BB1 "BB 2x5" "BREAD BOARD" -4747.24,6378.18 r0 top
BB2 "BB 2x5" "BREAD BOARD" -4348.31,5479.49 r180 top
BB3 "BB 2x5" "BREAD BOARD" -4747.38,5977.69 r0 top
BB4 "BB 2x5" "BREAD BOARD" -4848,6278 r270 top
BB5 "BB 2x5" "BREAD BOARD" -4948,5380 r90 top
BB6 "BB 2x5" "BREAD BOARD" -2025,1840 r0 top
BB7 "BB 2x5" "BREAD BOARD" -2026,1639 r0 top
BB8 "BB 2x5" "BREAD BOARD" -4348.67,5677.79 r180 top
BB9 "BB 2x5" "BREAD BOARD" -4347.9,6078.28 r180 top
BB10 "BB 2x5" "BREAD BOARD" -4748,5381 r0 top
BB11 "BB 2x5" "BREAD BOARD" -8198.07,5344.11 r0 top
BC1 "MC100EP016A(8_bit_counter)" LQFP_32pin -4201.32,2839.11 r135 top
BC2 "MC100EP016A(8_bit_counter)" LQFP_32pin -3468.06,2852.19 r135 top
BC3 "MC100EP016A(8_bit_counter)" LQFP_32pin -4503.01,1994.3 r135 top locked
BC4 "MC100EP016A(8_bit_counter)" LQFP_32pin -3764.15,1985.81 r135 top locked
BC5 "MC100EP016A(8_bit_counter)" LQFP_32pin -3491.74,789.14 r90 top locked
BC6 "74HC590PW(8_bit_counter)" TSSOP_16pin -984.47,777.49 r180 top
BMA "ADP3338(3V3 REG)" ADP3338 -5355.71,3032.41 r90 top
BMB "ADP3338(3V3 REG)" ADP3338 -2794.84,1947.57 r0 top
C1 "1uF" 0603 -4650.3,3768.44 r135 bottom
C2 "1uF" 0603 -4604.27,3816.73 r315 bottom
C3 "1uF" 0603 -627.54,3729.2 r270 bottom
C4 "1uF" 0603 -626,4040 r180 bottom
C5 "1uF" 0603 -4386.93,4014.29 r45 bottom
C6 "1uF" 0603 -4318.63,3561.92 r135 bottom
C7 "1nF" 0402 -1066.26,3591.76 r180 top
C8 "1uF" 0603 -3438.75,4310.17 r90 top
C9 "1uF" 0603 -981.16,3903.53 r180 bottom
C10 "1nF" 0402 -1066.26,3630.76 r180 top
C11 "1uF" 0603 -991,4027.58 r0 bottom
C12 "1uF" 0603 -1291,3475 r135 top
C13 "1uF" 0603 -1550,3723 r135 top
C14 "1uF" 0603 -1505.57,3455.42 r135 bottom
C15 "1uF" 0603 -4257.76,3710.28 r315 bottom locked
C16 "1uF" 0603 -4208.26,3759.77 r135 bottom locked
C17 "1uF" 0603 -4368.12,3512.42 r315 bottom
C18 "1nF" 0402 -1296.15,3679.2 r45 bottom
C19 "1nF" 0402 -489.74,3940.81 r180 top
C20 "1nF" 0402 -852.9,3939 r180 bottom
C21 "1nF" 0402 -4231.54,3869.65 r45 bottom
C22 "1nF" 0402 -4604.38,4103.77 r90 top
C23 "1nF" 0402 -1691.7,3338.61 r225 top
C24 "1nF" 0402 -3781.67,3740.05 r180 bottom
C25 "1nF" 0402 -3636.42,3624.64 r180 bottom
C26 ".01uF" 0603 -2315.66,2788.03 r135 bottom
C27 ".01uF" 0603 -2433.92,3636.91 r90 top
C28 "1uF" 0603 -1089.15,2823.68 r180 top
C29 ".1uF" 0603 -1086.2,2902.09 r180 top
C30 ".01uF" 0603 -1079.31,3172.11 r90 bottom
C31 ".01uF" 0603 -762.98,525.43 r180 bottom
C32 ".1uF" 0603 -1861.69,2270.9 r45 bottom
C33 ".1uF" 0603 -2504.29,3637.17 r270 top
C34 "1uF" 0603 -2663.65,3005.91 r45 bottom
C35 "1uF" 0603 -1400.14,3143.74 r0 bottom
C36 "1uF" 0603 -2370.23,3083.03 r45 top
C37 "1uF" 0603 -1426.14,2906.74 r0 bottom
C38 "1uF" 0603 -2414.92,3128.37 r45 top
C39 "1nF" 0402 -1959.9,2808.21 r135 bottom
C40 "1nF" 0402 -2383.17,2936.22 r135 bottom
C41 "1nF" 0402 -2152.31,2616.39 r135 bottom
C42 "1uF" 0603 -3679.76,3171.24 r315 bottom
C43 "1uF" 0603 -3599.05,3251.95 r135 bottom
C44 "1nF" 0402 -4420.69,3049.19 r135 bottom
C45 "1nF" 0402 -3695.22,3074.45 r135 bottom
C46 "1uF" 0603 -4004.22,3057.81 r45 top
C47 "1uF" 0603 -5389.21,2826.84 r0 top
C48 "1uF" 0603 -2081.52,2259 r180 top
C49 "1uF" 0603 -4329.36,3246.81 r135 bottom
C50 "1uF" 0603 -3539.14,2740.05 r45 bottom
C51 "1uF" 0603 -3263.25,3075.77 r225 top
C52 "1uF" 0603 -4230.81,2690.3 r45 bottom
C53 "1uF" 0603 -3493.29,2693.59 r225 bottom
C54 "1uF" 0603 -4277.19,2735.04 r45 bottom
C55 "1uF" 0603 -4581.74,1868.03 r45 bottom
C56 "1uF" 0603 -3002.19,1997 r270 top
C57 "1nF" 0402 -4803.83,2124.7 r135 bottom
C58 "1nF" 0402 -4062.55,2115.69 r135 bottom
C59 "1uF" 0603 -3792.16,1820.67 r45 bottom
C60 "1uF" 0603 -4630.31,2410.14 r135 bottom
C61 "1uF" 0603 -3481.65,1859.46 r315 bottom
C62 "1uF" 0603 -3971.91,2323.97 r135 bottom
C63 "1uF" 0603 -4308.22,2211.81 r45 top
C64 "1uF" 0603 -4535.98,1822.93 r225 bottom
C65 "1uF" 0603 -3837.07,1866.65 r45 bottom
C66 "1uF" 0603 -3534,2236 r225 top
C67 "1uF" 0603 -3893.08,2402.68 r315 bottom
C68 "1nF" 0402 -3452.96,1351.84 r0 top
C69 "1uF" 0603 -3801.81,1459.64 r0 bottom
C70 "1uF" 0603 -3221.47,628.59 r180 top
C71 "1uF" 0603 -4851.35,919.35 r270 top
C72 "1uF" 0603 -4951.01,881.24 r90 top
C73 "1uF" 0603 -3221.5,693.36 r180 top
C74 "1uF" 0603 -3768.26,680.92 r180 bottom
C75 "1uF" 0603 -2955.49,1243.57 r180 bottom
C76 "1uF" 0603 -2946.28,1110.91 r0 bottom
C77 "1uF" 0603 -3767.64,617.96 r0 bottom
C78 "1uF" 0603 -2649.16,878.26 r90 top
C79 "1uF" 0603 -1103.69,587.31 r135 top
C80 "1uF" 0603 -1373.6,640.06 r0 top
C81 "1uF" 0603 -2931,917.38 r0 top
C82 "1nF" 0402 -3201.86,1099.98 r0 top
C83 "1nF" 0402 -2812.12,1147 r180 top
C84 "1nF" 0402 -2811.39,1205.94 r270 top
C85 "1nF" 0402 -2806.21,653.19 r270 top
C86 "1uF" 0603 -6111.52,6574.45 r270 top
C87 "1uF" 0603 -6173.72,6574.71 r270 top
C88 "470uF" CAP_TH -1249,5489 r180 top locked
C89 ".1uF" 0603 -1367.82,4560 r180 top
C90 ".1uF" 0603 -2332.8,5299.48 r270 top
C91 ".1uF" 0603 -1729,4872.16 r180 bottom
C92 ".1uF" 0603 -1370,4375.86 r0 top
C93 ".1uF" 0603 -1983.49,4333.53 r180 bottom
C94 ".1uF" 0603 -1365.23,4926 r0 top
C95 ".1uF" 0603 -1366,4739 r180 bottom
C96 ".1uF" 0603 -1366,4739 r0 top
C97 ".1uF" 0603 -1724,4426.75 r180 top
C98 ".1uF" 0603 -1725.16,4578.53 r180 bottom
C99 ".1uF" 0603 -1365.23,4926 r180 bottom
C100 ".1uF" 0603 -1368,4560 r0 bottom
C101 ".1uF" 0603 -1727,4723.75 r180 top
C102 "1uF" 0603 -2439,5263 r270 top
C103 "1uF" 0603 -3124.07,1950.6 r270 top
C104 "1uF" 0603 -6206.52,3366 r180 top
C105 "1uF" 0603 -6208,3450 r180 top
C106 "1uF" 0603 -2567.84,3591.38 r270 top
C107 "1uF" 0603 -4344.51,3971.87 r225 bottom
C108 "1uF" 0603 -2231.1,2870.5 r315 bottom
C109 "1uF" 0603 -4414.99,3158.23 r135 bottom
C110 "1uF" 0603 -4724.31,2317.14 r135 bottom
C111 "1uF" 0603 -2322.93,5779.94 r270 top
C112 "1uF" 0603 -5347,2706 r180 top
C113 "10uF" 0603 -3568.75,4260.17 r270 top
C114 "1uF" 0603 -3801.81,1530.5 r180 bottom
C115 "1uF" 0603 -2439.93,5732.94 r270 top
C116 "1uF" 0603 -4810.6,1343.06 r90 bottom
C117 "22uF" CTC-D7343-31 -6573,3863 r0 top
C118 "1uF" 0603 -1497.6,589.06 r0 top
C119 "1uF" 0603 -1370,4375.86 r0 bottom
C120 ".1uF" 0603 -609,3065 r270 bottom
C121 "22uF" 0603 -2456,2963.8 r45 bottom
C122 ".1nF" 0603 -1012.38,3069.75 r180 bottom
C123 "22uF" 0603 -514.15,3064.96 r270 bottom
C124 "22uF" 0603 -297.22,2921.19 r270 top
C125 "4.7pF" 0603 -984.82,3282.35 r180 bottom
C400 "1uF" 0603 -8686,4972.69 r270 top
C401 "1uF" 0603 -9329.13,4963.22 r180 top
C402 "1uF" 0603 -8776.84,4974.17 r90 top
C403 "1uF" 0603 -9328.86,5028.65 r0 top
D1 "HSMS-2822" SOT23_3pin -626,3990 r270 top
D2 "HSMS-2822" SOT23_3pin -411,2907.23 r270 bottom
D3 "PMEG3050EP" SOD128 -665.92,2880.77 r270 bottom
D4 "PMEG3050EP" SOD128 -787.97,2876.83 r90 bottom
D5 "PMEG3050EP" SOD128 -7592.97,3727.05 r0 top
D6 "PMEG3050EP" SOD128 -7592.6,3497.05 r180 top
D7 "PMEG3050EP" SOD128 -7592.97,3610.05 r0 top
D8 "PMEG3050EP" SOD128 -7590.6,3380.05 r180 top
D8 "PMEG3050EP" SOD128 -776.16,3408.33 r0 bottom
DIS "ADP3338(3V3 REG)" ADP3338 -2093.8,5726 r0 top
F0 "8A 6V" FUSE1206-1 -8409.96,3291.4 r90 top
F1 "8A 6V" FUSE1206-1 -8386.33,3922.59 r270 top
FAN1 "5V DC FAN 40x40x10" 603-2014-ND -1821,7227 r180 top
FAN2 "5V DC FAN 40x40x10" 603-2014-ND -4585,7242 r180 top
FAN3 "Molex 2POS 4.2NN VERT TIN" "Molex 2POS" -1029.12,1590.7 r270 top (schematic designator J21)
FAN3 "5V DC FAN 40x40x10" 603-2014-ND -5082,367 r180 top
FAN4 "Molex 2POS 4.2NN VERT TIN" "Molex 2POS" -5225.38,1612.64 r270 top (schematic designator J20)
FAN4 "5V DC FAN 40x40x10" 603-2014-ND -1738,342 r180 top
FF1 "MC100LVEL29-D(BOUBLE DFF)" SOIC_20pin -2761.4,3177.87 r315 top locked
FF2 "SY10EP31VKG(SINGLE DFF)" MSOP8N -2989.18,785.68 r0 top
FF3 "SY89321LMG(LVPECL-LVTTL)" DFN_8PIN -2691.21,780.67 r0 top
FO1 "SY58032UMG(1-8 Fanout)" MLF_QFN_32PIN -4406.25,3759.77 r225 top locked
FO2 "SY89854UMG(1-4 LVPECL-LVPECL)" VFQFN_16PIN -2272.86,2828.74 r315 top
FO3 "85411AMILF(1:2 FANOUT LVPECL-LVDS)" SOIC_8pin -2117.5,2152.42 r90 bottom locked
FO4 "85411AMILF(1:2 FANOUT LVPECL-LVDS)" SOIC_8pin -1232.72,2155.12 r270 bottom
FO5 "ADP-2-9(PWR SPLITTER)" "PWR SPLITTER" -2606.12,1250 r0 top
FP1 "DISPLAY" DISPLAY -110,5140 r0 top
GPIO0 "GPIO0" SMD_TP -8521.94,4210.92 r90 top
GPIO1 "GPIO1" SMD_TP -8495.02,4435.67 r90 top
GPIO2 "GPIO2" SMD_TP -8517.26,4585.93 r90 top
J1 "SMA_R/A" SMA_R/A -256,3940 r0 top locked
J2 "2X1_RJ45" "2X1 RJ45" -276,2354 r90 top locked
J3 "MMCX" MMCX_VERTICAL_THROUGH_HOLE -4601.71,4230.33 r0 top
J4 "MMCX" MMCX_VERTICAL_THROUGH_HOLE -1797.11,3230.64 r225 top
J5 "LEMO_R/A" LEMO_R/A -390,3354 r0 top
J6 "SMA_R/A" SMA_R/A -217,1150 r0 top
J7 "LEMO_R/A" LEMO_R/A -390,500 r0 top
J9 "Molex 2POS 4.2NN VERT TIN" "Molex 2POS" -1903.81,6275.95 r270 top
J10 "Molex 2POS 4.2NN VERT TIN" "Molex 2POS" -4302.4,6592.52 r0 top
J11 "Molex 2POS 4.2NN VERT TIN" "Molex 2POS" -2927.28,5296.56 r180 top
J12 "2X1_RJ45" "2X1 RJ45" -288,4633 r90 top locked
J13 "2PIN JUMPER" "2 PIN HEADER" -2158,4916 r0 top
J14 "2PIN JUMPER" "2 PIN HEADER" -5227.3,2262.28 r180 top
J15 "Molex 4POS 3.96MM VERT TIN" "Molex 4POS" -7979.67,4223.01 r270 top
J17 "Molex 4POS 3.96MM VERT TIN" "Molex 4POS" -7973.02,2889.28 r90 top
J18 "Molex 2POS 4.2NN VERT TIN" "Molex 2POS" -3936.69,6270.94 r270 top
JTAG "ADP3338(3V3 REG)" ADP3338 -2112.8,5267 r0 top
JTAGDB "JTAG-SMT2-Digilent" "Digilent JTAG Programmer SMD" -9331,4050 r0 top locked
L1 "IND1008(10uH)" 1008 -757.43,3052 r0 bottom
L2 "IND1008(10uH)" 1008 -759.43,3297 r0 bottom
M1 "SN74AUP1T157DCKR(DEMUX)" TSSOP_6PIN -1727.68,4577.53 r180 top
MH1 "6-32 MH" "6-32 MH"#1 -7250,165 r0 top
MH2 "6-32 MH" "6-32 MH"#2 -4257,165 r0 top
MH3 "6-32 MH" "6-32 MH"#3 -1238,177 r0 top
MH4 "6-32 MH" "6-32 MH"#4 -1690,6990 r0 top
MH5 "6-32 MH" "6-32 MH"#5 -4560,6970 r0 top
MH6 "6-32 MH" "6-32 MH"#6 -7480,6980 r0 top
OA1 "LT1395CS5(OPAMP)" SOT23_5PIN -760.5,545.43 r180 top
OSC1 "127MHz OC" "127MHz OC" -803.28,3662 r270 top
PLL1 "SI5338A-B-GM(PLL)" QFN_24pin -1472.86,3529.89 r225 top
POT1 "3313J-1-103E(10KPOT)" 2KPOT -1539.01,2682.47 r270 top
POT2 "3313J-1-202E(2KPOT)" 2KPOT -1211.54,2680.77 r270 top
POT3 "3296W-1-103RLF(10 TURN 10K POT)" "10K POT" -4494.29,1283.9 r270 top
PWR1 "LT1945(DAUL 5V REG)" TFSOP_10pin -804.43,3174 r0 bottom
R1 "10K" 0402 -800.57,3761.68 r0 bottom
R2 "100" 0402 -1001.16,3611.76 r270 top
R3 "49.9" 0402 -1378.15,3734.2 r315 top
R4 "49.9" 0402 -1322.15,3678.2 r135 top
R5 "49.9" 0402 -1378.88,3760.2 r45 bottom
R6 "1.62K" 0402 -1396.51,3384.57 r315 bottom
R7 "1.62K" 0402 -1633.76,3647.4 r225 bottom
R8 "49.9" 0402 -4262.58,3900.84 r225 bottom
R9 "127" 0402 -4545.09,4000.99 r0 top
R10 "127" 0402 -4623.99,4044.99 r180 top
R11 "82.5" 0402 -4544.99,4044.99 r180 top
R12 "82.5" 0402 -4624.17,4001.15 r0 top
R13 "127" 0402 -1660.51,3454.57 r135 top
R14 "127" 0402 -1604.15,3398.2 r315 top
R15 "82.5" 0402 -1691.07,3423.2 r315 top
R16 "82.5" 0402 -1635.28,3367.41 r135 top
R17 "10K" 0402 -1582.83,2683.44 r0 bottom
R18 "49.9" 0402 -3781.13,3625.09 r180 bottom
R19 "49.9" 0402 -3763.15,3643.12 r270 top
R20 "49.9" 0402 -3762.77,3721.15 r90 top
R21 "49.9" 0402 -2033.06,3020.39 r315 bottom
R22 "49.9_1206" RC1206N1X -916.91,2793.17 r90 bottom
R23 "49.9" 0402 -2755.23,3123.11 r315 bottom
R24 "49.9" 0402 -2810.14,3177.49 r135 bottom
R25 "82.5" 0402 -1504.84,3142 r0 top
R26 "127" 0402 -1504.57,3142.81 r180 bottom
R27 "49.9" 0402 -2699.23,3153.11 r225 bottom
R28 "49.9" 0402 -2033.06,3047.11 r45 top
R29 "49.9" 0402 -1977.7,3102.48 r225 top
R30 "82.5" 0402 -1505.16,3096 r0 top
R31 "127" 0402 -1505.43,3095.19 r180 bottom
R32 "1K" 0402 -1328.13,2972.31 r180 bottom
R33 "4.02K" 0402 -1268.9,2781 r180 top
R34 "49.9" 0402 -3618.38,3606.65 r270 top
R35 "49.9" 0402 -3618.13,3528.2 r90 top
R36 "49.9" 0402 -3636.42,3510.64 r180 bottom
R37 "665" 0402 -1335.9,3039 r0 bottom
R38 "1.62K" 0402 -1182.65,3147.31 r270 bottom
R39 "4.02K" 0402 -1332,2764 r270 top
R40 "49.9" 0402 -2038.61,2729.94 r135 bottom
R41 "49.9" 0402 -2013.66,2729.59 r225 top
R42 "49.9" 0402 -1959.49,2783.61 r45 top
R43 "49.9" 0402 -2414.99,2904.4 r315 bottom
R44 "49.9" 0402 -2072.8,2670.78 r225 top
R45 "49.9" 0402 -2126.22,2616.88 r45 top
R46 "49.9" 0402 -2073.47,2695.71 r135 bottom
R47 "127" 0402 -2386.05,2567.63 r135 top
R48 "127" 0402 -2331.23,2513.03 r315 top
R49 "127" 0402 -2534.57,2716.74 r135 bottom
R50 "127" 0402 -2475.25,2658.83 r315 top
R51 "82.5" 0402 -2386.16,2568.19 r315 bottom
R52 "82.5" 0402 -2331.23,2513.03 r135 bottom
R53 "82.5" 0402 -2534.22,2717.58 r315 top
R54 "82.5" 0402 -2475.25,2658.83 r135 bottom
R55 "49.9" 0402 -4500.35,2970.03 r315 bottom
R56 "49.9" 0402 -3774.22,2994.17 r315 bottom
R57 "49.9" 0402 -4419.72,3024.4 r45 top
R58 "49.9" 0402 -4474.38,2969.96 r225 top
R59 "49.9" 0402 -3695.07,3049.01 r45 top
R60 "49.9" 0402 -3749.71,2994.09 r225 top
R61 "49.9" 0402 -4343.95,2758.75 r45 bottom
R62 "49.9" 0402 -3628.87,2761.58 r45 bottom
R63 "49.9" 0402 -4022.27,2770.78 r135 bottom
R64 "49.9" 0402 -3288.45,2784.43 r135 bottom
R65 "127" 0402 -3860.99,2867.66 r225 top
R66 "127" 0402 -3008.29,2892.95 r45 top
R67 "1K" 0402 -2288.99,2226.62 r90 bottom
R68 "49.9" 0402 -4373.91,2789.65 r45 bottom
R69 "82.5" 0402 -3829.35,2835.45 r225 top
R70 "82.5" 0402 -3043.64,2928.08 r45 top
R71 "1K" 0402 -2289,2146 r270 bottom
R72 "49.9" 0402 -4721.51,2207 r315 bottom
R73 "49.9" 0402 -3976.42,2201.05 r315 bottom
R74 "49.9" 0402 -4721.51,2180.27 r45 top
R75 "49.9" 0402 -4778.08,2123.71 r225 top
R76 "49.9" 0402 -3979.14,2170.49 r45 top
R77 "49.9" 0402 -4038.3,2111.97 r225 top
R78 "49.9" 0402 -4723.06,1832.95 r225 top
R79 "49.9" 0402 -3993.39,1825.29 r225 top
R80 "49.9" 0402 -4291.93,1850.87 r225 top
R81 "49.9" 0402 -3570.23,1826.99 r225 top
R82 "127" 0402 -4092.55,1937.27 r225 top
R83 "127" 0402 -3288.25,2132.93 r90 top
R84 "1K" 0402 -1188.69,1954.43 r0 top
R85 "49.9" 0402 -4753.5,1863.65 r225 top
R86 "82.5" 0402 -4129.19,1973.63 r225 top
R87 "82.5" 0402 -3331.32,2132.85 r270 top
R88 "1K" 0402 -1188.69,1909.43 r0 top
R89 "127" 0402 -3004.05,976.03 r0 top
R90 "127" 0402 -3056.61,1115.58 r0 bottom
R91 "49.9" 0402 -3156.1,1251.28 r0 bottom
R92 "82.5" 0402 -3042.39,1021.71 r0 top
R93 "82.5" 0402 -3074.97,1097.11 r90 top
R94 "49.9" 0402 -3174.12,1155.1 r270 top
R95 "49.9" 0402 -3174.12,1233.68 r90 top
R96 "49.9" 0402 -3741.33,836.07 r0 top
R97 "49.9" 0402 -3413.1,551.19 r90 top
R98 "127" 0402 -3197.58,793.06 r90 top
R99 "49.9" 0402 -3742.74,931.98 r0 top
R100 "49.9" 0402 -3741.64,881.98 r0 top
R101 "82.5" 0402 -3153.58,793.06 r90 top
R102 "49.9" 0402 -2806.58,912.87 r90 top
R103 "49.9" 0402 -2806.21,744.3 r270 top
R104 "49.9" 0402 -2806.58,822.87 r90 top
R105 "1K" 0402 -730.5,445.43 r0 top
R106 "4.02K" 0402 -926.69,580.31 r0 top
R107 "10K" 0402 -4715.48,6575.76 r270 top
R108 "10K" 0402 -2646.21,5293.52 r180 top
R109 "1K" 0402 -1969.31,4387.84 r0 bottom
R110 "10K" 0402 -2602,4672 r0 top
R111 "10K" 0402 -2561.84,4807 r0 top
R112 "10K" 0402 -2250.5,4730.14 r0 top
R113 "10" 0402 -2683.26,4672 r180 top
R114 "10" 0402 -2641,4806.84 r180 top
R115 "10" 0402 -2445,4856 r180 top
R116 "10" 0402 -2330.5,4730.14 r180 top
R117 "10K" 0402 -2334.84,4915.31 r180 top
R118 "10" 0402 -2335.16,4961.95 r180 top
R119 "10" 0402 -7913.28,6114.63 r0 bottom
R120 "10K" 0402 -7833,6115 r180 bottom
R121 "30.1K" 0402 -1001.35,3128.8 r180 bottom
R122 "10K" 0402 -929.7,3034.32 r270 bottom
R123 "10K" 0402 -893.25,3310.72 r270 bottom
R124 "30.9K" 0402 -976.94,3227.23 r0 bottom
R125 "1.62K" 0402 -1573.76,3643.4 r45 bottom
RA1 "49.9" 0402 -8936.29,4973.06 r90 top
RA2 "49.9" 0402 -9028.07,4927.12 r180 top
RA3 "49.9" 0402 -8450.81,4629.53 r0 bottom
RAWPWR1 "ECS60Us05(AC-DC)" ECS60US05 -7000,1488 r0 top locked
RF "ADP3338(3V3 REG)" ADP3338 -3234.49,4257.77 r0 top
RF3V "RF3V3" "Test Point" -2994.49,4257.77 r180 top (schematic designator TP18)
RM "ADP3338(3V3 REG)" ADP3338 -2228.56,3585.83 r0 top
RM3V "RM3V3" "Test Point" -1990.56,3583.83 r0 top (schematic designator TP19)
RPI_5V "RPI5V" "Test Point" -5891,6696 r270 top (schematic designator TP?)
SR1 "SN74LV594APWR(Shift Register)" TSSOP_16pin -4373.68,3198.94 r135 top
SR2 "SN74LV594APWR(Shift Register)" TSSOP_16pin -3638.83,3212.96 r135 top
SR3 "SN74LV594APWR(Shift Register)" TSSOP_16pin -4670.65,2353.93 r135 top locked
SR4 "SN74LV594APWR(Shift Register)" TSSOP_16pin -3930.68,2347.22 r135 top locked
st "Zelflex_QR_Stencil_10in" Zelflex_QR_Stencil_10in 1377.43,8582.35 r90 top locked
SW2 "E101SD1AQE" E101SD1AQE -9437,3503.94 r0 top locked
TP1 "RF1_N" SMD_TP -1399.58,3644.48 r135 top
TP2 "RF1_P" SMD_TP -1413.01,3657.92 r135 top
TP3 "HYSA" "Test Point" -1691,2701 r270 top
TP4 "RM1_P" SMD_TP -1958.72,3040.85 r45 top
TP5 "RM1_N" SMD_TP -1971.32,3028.13 r135 top
TP6 "THRES" "Test Point" -1058.25,2699.83 r0 top
TP7 "RM2_P" SMD_TP -2020.75,2802.44 r45 top
TP8 "RM2_N" SMD_TP -2033.11,2789.83 r45 top
TP9 "RM3_P" SMD_TP -1045,2236 r90 top
TP10 "RM3_N" SMD_TP -1045,2216 r135 top
TP11 "BMA1" SMD_TP -3781.35,2815.45 r135 top
TP12 "BMA2_P" SMD_TP -1020,2356 r90 bottom
TP13 "BMA2_N" SMD_TP -1020,2377 r90 bottom
TP14 "BMB1" SMD_TP -4048.23,1919.59 r135 top
TP15 "BMB2_P" SMD_TP -1045.06,2429.9 r90 top
TP16 "BMB2_N" SMD_TP -1044.68,2412.2 r90 top
TP17 "10MHz" SMD_TP -1228.6,791.16 r90 top
TP20 "BMA3V3" "Test Point" -5352.74,3274.5 r90 top
TP21 "BMB3V3" "Test Point" -2555.13,1946.86 r0 top
TP24 "JTAG3V3" "Test Point" -1870.8,5265 r0 top
TP25 "TEST5V" "Test Point" -4694.12,1137 r90 top
TP30 "VCO" "Test Point" -4297.63,1282.3 r90 top
U1 "MAX9601EUP(NIM-LVPECL)" TSSOP_20pin -1300.14,3023.74 r90 top locked
U2 "CVCO55CL-0490-0540(508.9MHz VCO)" "QFN_16pin Variant" -4146.15,1633 r270 top
U3 "KAT1108E( 8BIT DIP SWITCH)" "8 BIT DIP SWITCH" -4312.12,755 r90 top
U4 "SN74HC682DW(2X8 COM)" SOIC_20pin -1238.79,777.77 r270 bottom locked
U5 "KAT1108E( 8BIT DIP SWITCH)" "8 BIT DIP SWITCH" -2074.6,794.06 r90 top
U6 "Display CONN" "DISPLAY CONN" -1299.37,5836 r90 top locked
U7 "JTAG 14PIN" JTAG_14PIN_2MM_VERT -2278.74,4484.37 r0 top

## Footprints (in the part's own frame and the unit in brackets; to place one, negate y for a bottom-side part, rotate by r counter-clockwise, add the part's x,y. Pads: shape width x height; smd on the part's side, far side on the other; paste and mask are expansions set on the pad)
"2 PIN HEADER" [mil]
  round 70 hole 50: 1(-50,0) 2(50,0)
  silkscreen extent -100,-50 100,50, body extent -100,-50 100,50, height 470
2KPOT [mm] "TRIMMER 2K OHM 0.125W SMD"
  rect 1.1x1.6 smd: 1(-1.15,-1.45) 3(1.15,-1.45)
  rect 1.6x1.6 smd: 2(0,1.45)
  silkscreen extent -1.6,-1.75 1.6,1.75, body extent -1.6,-1.75 1.6,1.75, height 2.77
"2X1 RJ45" [mm] "DOUBLE_RIGHT ANGLE_RJ-45"
  round 1.3 hole 0.9: 1(-4.445,6.35) 2(-3.175,8.89) 3(-1.905,6.35) 4(-0.635,8.89) 5(0.635,6.35) 6(1.905,8.89) 7(3.175,6.34) 8(4.445,8.89) 9(4.445,15.494) 10(3.175,12.944) 11(1.905,15.494) 12(0.635,12.954) 13(-0.635,15.494) 14(-1.905,12.954) 15(-3.175,15.494) 16(-4.445,12.954)
  round 2 hole 1.7: 17(-8.509,-4.572) 18(8.509,-4.572) 19(-7.823,9.144) 20(7.823,6.35) 21(-8.509,15.469) 22(8.509,11.43)
  round 3.302 hole 3.302 unplated: 23(-6.35,0) 24(5.715,0)
  silkscreen extent -9.14,-11.43 9.14,18.29, body extent -9.36,-10.87 9.36,17.63, height 25.15
"6-32 MH"#1 [mil] "6-32 MOUNTING HOLE"
  round 280 hole 152: 1(-21.76,10)
"6-32 MH"#2 [mil] "6-32 MOUNTING HOLE"
  round 280 hole 152: 1(7,10)
"6-32 MH"#3 [mil] "6-32 MOUNTING HOLE"
  round 280 hole 152: 1(-12,-2)
"6-32 MH"#4 [mil] "6-32 MOUNTING HOLE"
  round 280 hole 152: 1(440,34.89)
"6-32 MH"#5 [mil] "6-32 MOUNTING HOLE"
  round 280 hole 152: 1(310,55)
"6-32 MH"#6 [mil] "6-32 MOUNTING HOLE"
  round 280 hole 152: 1(230,45)
"8 BIT DIP SWITCH" [mm] "24.30mm X 10mm X 6.70mm PITHC 2.54mm"
  round 1.2 hole 0.8: 1(3.81,8.89) 2(3.81,6.35) 3(3.81,3.81) 4(3.81,1.27) 5(3.81,-1.27) 6(3.81,-3.81) 7(3.81,-6.35) 8(3.81,-8.89) 9(-3.81,8.89) 10(-3.81,-8.89)
  silkscreen extent -5,-12.15 5.62,12.15, body extent -5,-12.15 5,12.15, height 6.7
"10K POT" [mil] "TRIMMER 10K OHM 0.5W PC PIN"
  round 35 hole 25: 1(-100,0) 2(0,0) 3(100,0)
  silkscreen extent -195,-100 195,100, body extent -190,-95 190,95, height 455
"127MHz OC" [mm]
  rect 1.5x1.6 smd: 1(-2.54,-1.95) 2(0,-1.95) 3(2.54,-1.95) 4(2.54,1.95) 5(0,1.95) 6(-2.54,1.95)
  silkscreen extent -3.93,-2.51 3.28,2.57, body extent -3.27,-2.53 3.3,2.58, height 2
0402 [mm] "0.039\" L x 0.020\" W (1.00mm x 0.50mm)"
  rect 0.6x0.64 smd: 1(-0.48,0) 2(0.48,0)
  body extent -0.5,-0.25 0.5,0.25, height 0.5
0603 [mm] "0.063\" L x 0.031\" W (1.60mm x 0.80mm)"
  rect 0.8x0.95 smd: 1(-0.825,0) 2(0.825,0)
  silkscreen extent -0.05,-0.37 0.05,0.38, body extent -0.8,-0.4 0.8,0.4, height 0.5
603-2014-ND [mil] "FAN AXIAL 40X40X10MM 5V WIRE"
  body extent 0,0 1575,394, height 1575
1008 [mm] "0.098\" L x 0.079\" W (2.50mm x 2.00mm)"
  rect 1.65x2.05 smd: 1(-1.524,0) 2(1.524,0)
  body extent -1.25,-1 1.25,1, height 1
ADP3338 [mm] "SOT223, 4-Leads, Body 6.50x7.00mm (avg), Pitch 2.30mm, IPC Medium Density"
  rect 2.2x1 smd: 1(-2.85,2.3) 2(-2.85,0) 3(-2.85,-2.3)
  rect 2.2x3.2 smd: 4(2.85,0)
  silkscreen extent -2.98,-3.25 1.45,3.47, body extent -1.75,-3.25 1.75,3.25, height 1.6
"BREAD BOARD" [mil] "2X5 .1IN BREAD BAORD"
  rect 75x75 hole 40: 1(0,0) 2(100,0) 3(200,0) 4(300,0) 5(400,0) 6(0,-100) 7(100,-100) 8(200,-100) 9(300,-100) 10(400,-100)
CAP_TH [mil]
  round 50 hole 28: 1(0,0) 2(197,0)
  silkscreen extent -150,-250 350,250, body extent -146,-246 346,246, height 787
CTC-D7343-31 [mm] "Capacitor Tantal Chip D - 7343, H=2.8mm"
  rrect50% 2.7x2.5 smd: 1(-3.275,0) 2(3.275,0)
  silkscreen extent -4.45,-2.15 3.65,2.15, body extent -4,-2.15 4,2.15, height 2.81
DFN_8PIN [mm] "DFN, 8-Leads, Body 2.00x2.00mm, Pitch 0.50mm, Thermal Pad 1.55x1.55mm, IPC Medium Density"
  oval 0.75x0.305 smd mask+0.051: 1(-1,0.75) 2(-1,0.25) 3(-1,-0.25) 4(-1,-0.75) 5(1,-0.75) 6(1,-0.25) 7(1,0.25) 8(1,0.75)
  rect 0.6x1.2 smd: 9(0,0)
  silkscreen extent -1.35,-1.02 1.02,1.35, body extent -1,-1 1,1, height 0.9
"Digilent JTAG Programmer SMD" [mm]
  rect 3.5x3 smd: 1(0,0) 2(5,0) 3(10,0) 4(15,0) 8(15,19.5) 9(10,19.5) 10(5,19.5) 11(0,19.5)
  rect 3x3.5 smd: 5(17.75,4.75) 6(17.75,9.75) 7(17.75,14.75)
  Top Layer - SIG1 keep-out region: -4,12.2 -1.4,12.2 -1.4,14.4 -4,14.4
  Top Layer - SIG1 keep-out region: -4,5.1 -1.4,5.1 -1.4,7.3 -4,7.3
  body extent -4.9,-0.95 18.85,20.55, height 4.31
DISPLAY [mil] "DISPLAY"
  body extent 0,0 146,2047, height 1772
"DISPLAY CONN" [mil] "DISPLAY"
  rect 60x60 hole 41: 1(0,0)
  round 60 hole 41: 2(0,-100) 3(100,0) 4(100,-100) 5(200,0) 6(200,-100) 7(300,0) 8(300,-100) 9(400,0) 10(400,-100) 11(500,0) 12(500,-100) 13(600,0) 14(600,-100) 15(700,0) 16(700,-100) 17(800,0) 18(800,-100) 19(900,0) 20(900,-100)
  silkscreen extent -50,-150 955,50, body extent -51,-151 950,54, height 413
E101SD1AQE [mm] "SWITCH TOGGLE SPDT 7.5A 125V"
  oval 3x2.6 hole 1.85 paste+0: 1(12.7,-2.16) 2(12.7,2.54) 3(12.7,7.24) 4(0,0) 5(0,5.08)
  body extent -18.88,-3.9 13.3,8.8, height 7.01
ECS60US05 [mm] "AC-DC Convertor, 5V at 8A"
  round 8 hole 4: 1(-34.9,-22.16) 2(-34.9,22.24) 3(34.9,22.24) 4(34.9,-22.24)
  body extent -38.25,-25.72 37.95,25.33, height 25.73
FUSE1206-1 [mm] "Chip Fuse, Body 3.2x1.6mm"
  rect 1x1.8 smd: 1(-1.4,0) 2(1.4,0)
  silkscreen extent -0.81,-0.76 0.81,0.76, body extent -1.52,-0.76 1.51,0.76, height 0.41
JTAG_14PIN_2MM_VERT [mil]
  rect 60x60 hole 33: 1(-236.22,-39.37)
  round 60 hole 33: 2(-236.22,39.37) 3(-157.48,-39.37) 4(-157.48,39.37) 5(-78.74,-39.37) 6(-78.74,39.37) 7(0,-39.37) 8(0,39.37) 9(78.74,-39.37) 10(78.74,39.37) 11(157.48,-39.37) 12(157.48,39.37) 13(236.22,-39.37) 14(236.22,39.37)
  silkscreen extent -339,-106 339,106, body extent -339,-106 339,106, height 209
LEMO_R/A [mm] "EPA.00.250.NTN, RIGHT ANGLE"
  round 1 hole 0.7: 1(0,0)
  round 1.2 hole 1: 2(-2.54,2.54) 3(2.54,2.54) 4(-2.54,-2.54) 5(2.54,-2.54)
  silkscreen extent -3.51,-3.51 3.51,3.51, body extent -3.5,-3.5 14,3.5, height 7
LQFP_32pin [mm] "LQFP, 32-Leads, Body 7.00x7.00mm, Pitch 0.80mm, IPC Medium Density"
  rect 1.4x0.4 smd: 1(-4.2,2.8)
  oval 1.4x0.4 smd: 2(-4.2,2) 3(-4.2,1.2) 4(-4.2,0.4) 5(-4.2,-0.4) 6(-4.2,-1.2) 7(-4.2,-2) 8(-4.2,-2.8) 17(4.2,-2.8) 18(4.2,-2) 19(4.2,-1.2) 20(4.2,-0.4) 21(4.2,0.4) 22(4.2,1.2) 23(4.2,2) 24(4.2,2.8)
  oval 0.4x1.4 smd: 9(-2.8,-4.2) 10(-2,-4.2) 11(-1.2,-4.2) 12(-0.4,-4.2) 13(0.4,-4.2) 14(1.2,-4.2) 15(2,-4.2) 16(2.8,-4.2) 25(2.8,4.2) 26(2,4.2) 27(1.2,4.2) 28(0.4,4.2) 29(-0.4,4.2) 30(-1.2,4.2) 31(-2,4.2) 32(-2.8,4.2)
  silkscreen extent -4.32,-3.1 3.1,3.67, body extent -3.5,-3.5 3.5,3.5, height 1.6
MLF_QFN_32PIN [mil] "PQFN, 32-Leads, Body 5.00x5.00mm, Pitch 0.50mm, Thermal Pad 3.10x3.10mm, IPC Medium Density"
  oval 30x13 smd mask+2: 1(-102,68.9) 2(-102,49.21) 3(-102,29.53) 4(-102,9.84) 5(-102,-9.84) 6(-102,-29.53) 7(-102,-49.21) 8(-102,-68.9) 17(102,-68.9) 18(102,-49.21) 19(102,-29.53) 20(102,-9.84) 21(102,9.84) 22(102,29.53) 23(102,49.21) 24(102,68.9)
  oval 13x30 smd mask+2: 9(-68.9,-102) 10(-49.21,-102) 11(-29.53,-102) 12(-9.84,-102) 13(9.84,-102) 14(29.53,-102) 15(49.21,-102) 16(68.9,-102) 25(68.9,102) 26(49.21,102) 27(29.53,102) 28(9.84,102) 29(-9.84,102) 30(-29.53,102) 31(-49.21,102) 32(-68.9,102)
  rect 122.05x122.05 smd: 33(0,0)
  silkscreen extent -135,-98 98,105, body extent -98,-98 98,98, height 33
MMCX_VERTICAL_THROUGH_HOLE [mm]
  round 1.24 hole 0.84: 1(0,0) 2(-1.27,-1.27) 3(1.27,-1.27) 4(1.27,1.27) 5(-1.27,1.27)
  silkscreen extent -1.73,-1.73 1.73,1.73, body extent -1.73,-1.73 1.73,1.73, height 4.42
"Molex 2POS" [mil] "CONN HEADER 2POS 4.2MM VERT TIN"
  round 80 hole 60: 1(-108.5,0) 2(108.5,0)
  silkscreen extent -189,-110 192,110, body extent -188,-110 192,110, height 500
"Molex 4POS" [mm] "CONN HEADER 4POS 3.96MM VERT TIN"
  round 2.5 hole 1.8: 1(0,0) 2(3.96,0) 3(7.92,0) 4(11.88,0)
  silkscreen extent -1.6,-5.2 13.5,5.6, body extent -1.64,-5.15 13.44,5.6, height 13.85
MSOP8N [mm]
  rrect50% 1.4x0.4 smd mask+0.051: 1(-2.225,0.975)
  oval 1.4x0.4 smd mask+0.051: 2(-2.225,0.325) 3(-2.225,-0.325) 4(-2.225,-0.975) 5(2.225,-0.975) 6(2.225,-0.325) 7(2.225,0.325) 8(2.225,0.975)
  silkscreen extent -2.35,-1.5 1.13,1.85, body extent -1.5,-1.5 1.5,1.5, height 1.11
"PWR SPLITTER" [mm] "SOTFL, 6-Leads, Body 7.87x6.91mm, Pitch 2.54mm, IPC Medium Density"
  rect 1x0.9 smd: 1(-3.225,2.54) 2(-3.225,0) 3(-3.225,-2.54) 4(3.225,-2.54) 5(3.225,0) 6(3.225,2.54)
  silkscreen extent -3.35,-3.95 2.35,3.95, body extent -2.8,-3.94 2.8,3.94, height 4.11
QFN_16pin [mil] "QFN, 16-Leads, Body 3.00x3.00mm, Pitch 0.50mm, Thermal Pad 1.50x1.50mm, IPC Medium Density"
  rect 40x11 smd paste+0: 1(-65,29.53)
  oval 40x11 smd paste+0: 2(-65,9.84) 3(-65,-9.84) 4(-65,-29.53)
  oval 11x40 smd: 5(-29.53,-65) 6(-9.84,-65) 7(9.84,-65) 8(29.53,-65) 13(29.53,65) 14(9.84,65) 15(-9.84,65) 16(-29.53,65)
  oval 40x11 smd: 9(65,-29.53) 10(65,-9.84) 11(65,9.84) 12(65,29.53)
  rect 59.06x59.06 smd: 17(0,0)
  silkscreen extent -75,65 -65,75, body extent -59,-59 59,59, height 31
"QFN_16pin Variant" [mil] "QFN, 16-Leads, Body 12.70x12.70mm, Pitch 2.54mm, Variant"
  rect 52x48 smd: 1(115,0) 2(215,-4) 3(315,0) 4(415,0) 9(380,500) 10(280,504) 11(180,500) 12(80,500)
  rect 48x52 smd: 5(500,105) 6(500,205) 7(500,305) 8(500,405) 14(-4,311.06) 15(0,215) 16(0,115)
  rect 48.03x51.97 smd: 13(0,415)
  silkscreen extent 2,-64 514,507, body extent 0,0 500,500, height 150
QFN_24pin [mm] "QFN, 24-Leads, Body 4.00x4.00mm, Pitch 0.50mm, Thermal Pad 2.50x2.50mm, IPC Medium Density"
  rect 0.8x0.25 smd: 1(-1.925,1.25)
  oval 0.8x0.25 smd: 2(-1.925,0.75) 3(-1.925,0.25) 4(-1.925,-0.25) 5(-1.925,-0.75) 6(-1.925,-1.25) 13(1.925,-1.25) 14(1.925,-0.75) 15(1.925,-0.25) 16(1.925,0.25) 17(1.925,0.75) 18(1.925,1.25)
  oval 0.25x0.8 smd: 7(-1.25,-1.925) 8(-0.75,-1.925) 9(-0.25,-1.925) 10(0.25,-1.925) 11(0.75,-1.925) 12(1.25,-1.925) 19(1.25,1.925) 20(0.75,1.925) 21(0.25,1.925) 22(-0.25,1.925) 23(-0.75,1.925) 24(-1.25,1.925)
  rect 2.5x2.5 smd: 25(0,0)
  silkscreen extent -2.92,-2.15 2.15,2.15, body extent -2,-2 2,2, height 0.8
RC1206N1X [mm] "Chip resistor 1206"
  rect 1x1.75 smd: 1(-1.55,0) 2(1.55,0)
  silkscreen extent -0.58,-0.76 0.58,0.76, body extent -1.55,-0.76 1.55,0.76, height 0.56
RPI_2/RPI_3 [mil]
  rrect50% 65x65 hole 35.43 paste-50: 1(330.12,184.65)
  round 65 hole 35.43 paste-50: 2(330.12,84.65) 3(430.12,184.65) 4(430.12,84.65) 5(530.12,184.65) 6(530.12,84.65) 7(630.12,184.65) 8(630.12,84.65) 9(730.12,184.65) 10(730.12,84.65) 11(830.12,184.65) 12(830.12,84.65) 13(930.12,184.65) 14(930.12,84.65) 15(1030.12,184.65) 16(1030.12,84.65) 17(1130.12,184.65) 18(1130.12,84.65) 19(1230.12,184.65) 20(1230.12,84.65) 21(1330.12,184.65) 22(1330.12,84.65) 23(1430.12,184.65) 24(1430.12,84.65) 25(1530.12,184.65) 26(1530.12,84.65) 27(1630.12,184.65) 28(1630.12,84.65) 29(1730.12,184.65) 30(1730.12,84.65) 31(1830.12,184.65) 32(1830.12,84.65) 33(1930.12,184.65) 34(1930.12,84.65) 35(2030.12,184.65) 36(2030.12,84.65) 37(2130.12,184.65) 38(2130.12,84.65) 39(2230.12,184.65) 40(2230.12,84.65)
  round 244.09 hole 108.27 mask+3.94: MH2(133.86,2062.99) MH3(2417.32,145.67)
  silkscreen extent 0,0 3387,2205, body extent -2,1 3479,2373, height 958
SMA_R/A [mil] "Panel Mount, Bulkhead; Through Hole,RIGHT ANGLE"
  round 100 hole 70: 1(0,0) 2(-100,100) 3(100,100) 4(-100,-100) 5(100,-100)
  silkscreen extent -160,-160 160,160, body extent -157,-157 608,158, height 411
SMD_TP [mil] "SURFACE MOUNT TEST PAD"
  oct 11.54x11.54 smd: 1(0,0)
SOD128 [mm] "2-Leads, Body 2.7x4.0mm (max), IPC Medium Density"
  rrect50% 1.2x1.9 smd: 1(-2.2,0) 2(2.2,0)
  body extent -2,-1.35 2,1.35, height 1.1
SOIC_8pin [mm] "SOIC, 8-Leads, Body 5.00x4.00mm, Pitch 1.27mm, IPC Medium Density"
  rect 1.45x0.6 smd: 1(-2.725,1.905)
  oval 1.45x0.6 smd: 2(-2.725,0.635) 3(-2.725,-0.635) 4(-2.725,-1.905) 5(2.725,-1.905) 6(2.725,-0.635) 7(2.725,0.635) 8(2.725,1.905)
  silkscreen extent -2.85,-2.5 1.6,2.88, body extent -2,-2.5 2,2.5, height 1.63
SOIC_20pin [mm] "SOIC, 20-Leads, Body 12.80x7.50mm, Pitch 1.27mm, IPC Medium Density"
  rect 1.7x0.6 smd: 1(-4.85,5.715)
  oval 1.7x0.6 smd: 2(-4.85,4.445) 3(-4.85,3.175) 4(-4.85,1.905) 5(-4.85,0.635) 6(-4.85,-0.635) 7(-4.85,-1.905) 8(-4.85,-3.175) 9(-4.85,-4.445) 10(-4.85,-5.715) 11(4.85,-5.715) 12(4.85,-4.445) 13(4.85,-3.175) 14(4.85,-1.905) 15(4.85,-0.635) 16(4.85,0.635) 17(4.85,1.905) 18(4.85,3.175) 19(4.85,4.445) 20(4.85,5.715)
  silkscreen extent -4.97,-6.4 3.6,6.69, body extent -3.75,-6.4 3.75,6.4, height 2.5
SOT23_3pin [mm] "SOT23, 3-Leads, Body 3.00x2.50mm, Pitch 1.00mm, IPC Medium Density"
  rect 0.95x0.7 smd: 1(-1.225,1) 2(-1.225,-1) 3(1.225,0)
  silkscreen extent -1.35,-1.5 0.75,2.03, body extent -0.75,-1.5 0.75,1.5, height 1
SOT23_5PIN [mm] "SOT23, 5-Leads, Body 3.00x2.80mm, Pitch 1.00mm, IPC Medium Density"
  rect 1.1x0.7 smd: 1(-1.3,1) 2(-1.3,0) 3(-1.3,-1) 4(1.3,-1) 5(1.3,1)
  silkscreen extent -1.42,-1.5 0.75,2.02, body extent -0.75,-1.5 0.75,1.5, height 1
SOT223_5pin [mm] "SOT223, 5-Leads, Body 6.50x7.00mm (avg), Pitch 1.50mm, IPC Medium Density"
  rect 1.85x1 smd: 1(-3,2.25) 2(-3,0.75) 3(-3,-0.75) 4(-3,-2.25)
  rect 1.85x3.2 smd: 5(3,0)
  silkscreen extent -3.13,-3.25 1.8,3.42, body extent -1.75,-3.25 1.75,3.25, height 1.6
"Test Point" [mil] "TEST POINT PC MINI .040\"D BLACK"
  round 70 hole 50: 1(0,0)
  body extent -50,-50 50,50, height 180
TFSOP_10pin [mm] "TSSOP, 10-Leads, Body 3.00x3.00mm, Pitch 0.50mm, IPC Medium Density"
  rect 1.4x0.33 smd mask+0.051: 1(-2.2,1)
  oval 1.4x0.33 smd mask+0.051: 2(-2.2,0.5) 3(-2.2,0) 4(-2.2,-0.5) 5(-2.2,-1) 6(2.2,-1) 7(2.2,-0.5) 8(2.2,0) 9(2.2,0.5) 10(2.2,1)
  silkscreen extent -2.32,-1.5 1.1,1.85, body extent -1.5,-1.5 1.5,1.5, height 1
TO220H [mil] "TO-220 horizontal"
  oval 70x95 hole 39.37: 1(-100,-310) 2(0,-310) 3(100,-310)
  rect 410x600 smd paste-500: 2(0,125)
  round 157.48 hole 125.98 mask+47.24: 2(0,310)
  silkscreen extent -213,-261 213,433, body extent -200,-320 200,420, height 197
TSSOP_6PIN [mm] "TSOP, 6-Leads, Body 2.15x1.40mm, Pitch 0.65mm, IPC Medium Density"
  oval 0.95x0.381 smd mask+0.076: 1(-1.1,0.65) 2(-1.1,0) 3(-1.1,-0.65) 4(1.1,-0.65) 5(1.1,0) 6(1.1,0.65)
  silkscreen extent -1.22,-1.1 0.7,1.57, body extent -0.7,-1.1 0.7,1.1, height 1.1
TSSOP_16pin [mm] "TSOP, 16-Leads, Body 5.00x4.40mm, Pitch 0.65mm, IPC Medium Density"
  rect 1.4x0.45 smd: 1(-2.975,2.275)
  oval 1.4x0.45 smd: 2(-2.975,1.625) 3(-2.975,0.975) 4(-2.975,0.325) 5(-2.975,-0.325) 6(-2.975,-0.975) 7(-2.975,-1.625) 8(-2.975,-2.275) 9(2.975,-2.275) 10(2.975,-1.625) 11(2.975,-0.975) 12(2.975,-0.325) 13(2.975,0.325) 14(2.975,0.975) 15(2.975,1.625) 16(2.975,2.275)
  silkscreen extent -3.1,-2.5 1.88,3.17, body extent -2.2,-2.5 2.2,2.5, height 1
TSSOP_20pin [mm] "TSOP, 20-Leads, Body 6.50x4.50mm, Pitch 0.65mm, IPC Medium Density"
  rect 1.35x0.4 smd: 1(-3,2.925)
  oval 1.35x0.4 smd: 2(-3,2.275) 3(-3,1.625) 4(-3,0.975) 5(-3,0.325) 6(-3,-0.325) 7(-3,-0.975) 8(-3,-1.625) 9(-3,-2.275) 10(-3,-2.925) 11(3,-2.925) 12(3,-2.275) 13(3,-1.625) 14(3,-0.975) 15(3,-0.325) 16(3,0.325) 17(3,0.975) 18(3,1.625) 19(3,2.275) 20(3,2.925)
  silkscreen extent -3.12,-3.25 1.93,3.8, body extent -2.25,-3.25 2.25,3.25, height 1
VFQFN_16PIN [mm] "QFN, 16-Leads, Body 3.00x3.00mm, Pitch 0.50mm, Thermal Pad 1.55x1.55mm, IPC Medium Density"
  rect 0.8x0.25 smd: 1(-1.425,0.75)
  oval 0.8x0.25 smd: 2(-1.425,0.25) 3(-1.425,-0.25) 4(-1.425,-0.75) 9(1.425,-0.75) 10(1.425,-0.25) 11(1.425,0.25) 12(1.425,0.75)
  oval 0.25x0.8 smd: 5(-0.75,-1.425) 6(-0.25,-1.425) 7(0.25,-1.425) 8(0.75,-1.425) 13(0.75,1.425) 14(0.25,1.425) 15(-0.25,1.425) 16(-0.75,1.425)
  rect 1.55x1.55 smd: 17(0,0)
  silkscreen extent -2.42,-1.65 1.65,1.65, body extent -1.5,-1.5 1.5,1.5, height 0.8
Zelflex_QR_Stencil_10in [mil]
  body extent -10001,-1 0,12282, height 591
